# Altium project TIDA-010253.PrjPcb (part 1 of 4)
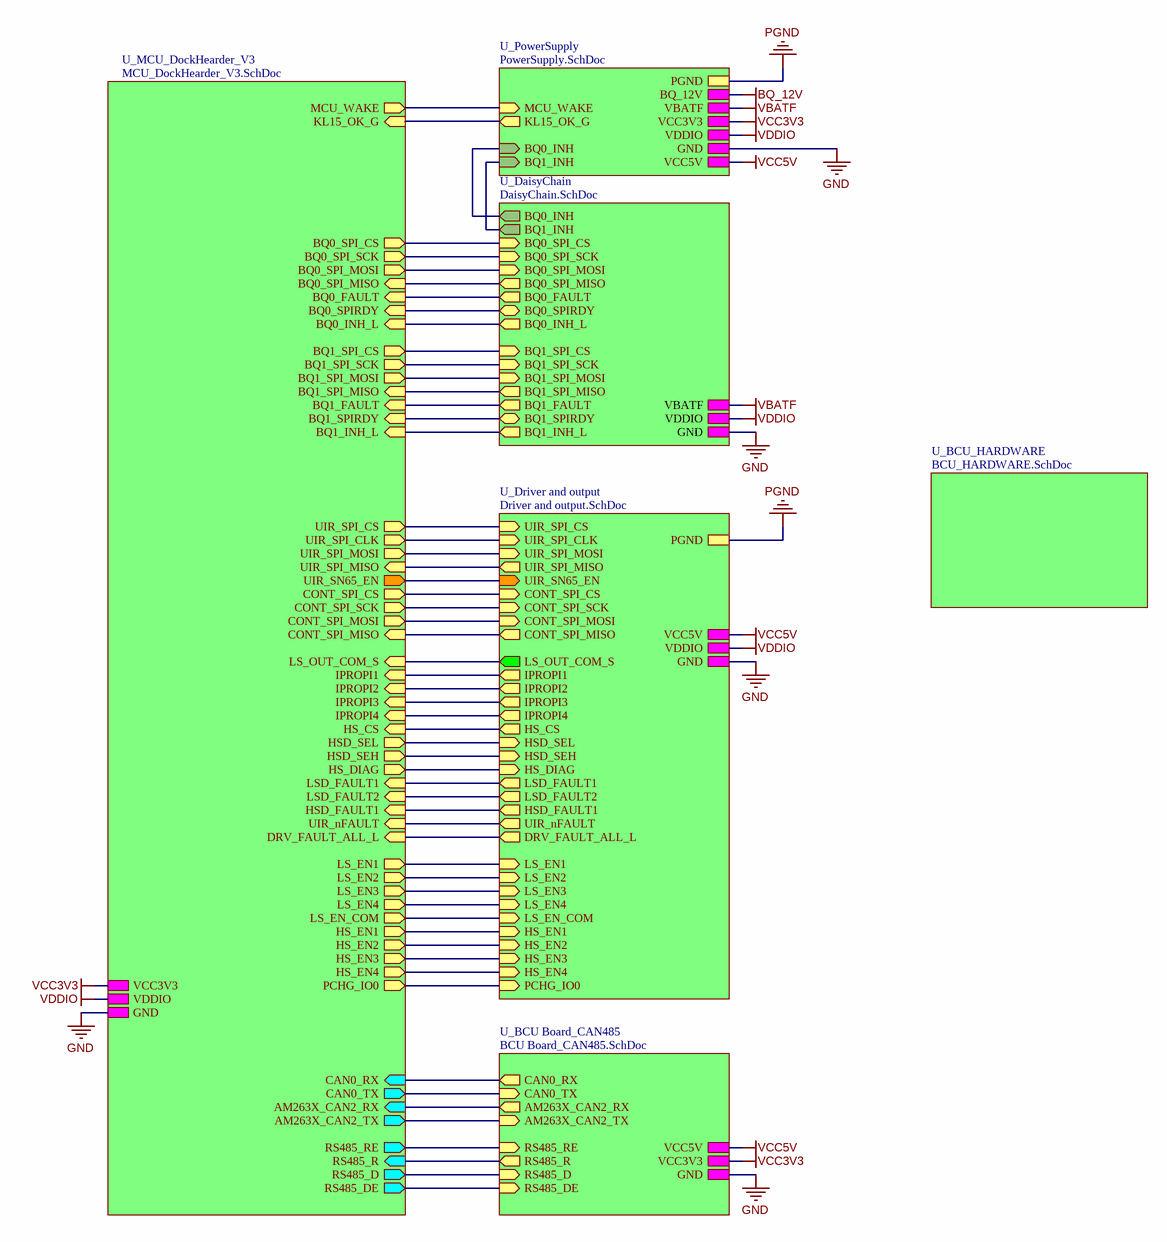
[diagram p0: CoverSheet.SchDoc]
TID: TIDA-010253; TechSupport: http://www.ti.com/support; SCH_Rev: E1; PRJ_Title: Battery Control Unit Reference Design for Energy Storage Systems; PRJ_Number: TIDA-010253; PRJ_Engineer: Enter name of project lead; PRJ_Customer: Public Release; PCB_Rev: E1; PCB_Layout: Junhua Yan; CopyrightYear: 2018
7 sheets, 527 parts. Net scope: hierarchical (ports join the sheet entries above them; power ports are global).
Board file: TIDA-010253.PcbDoc
Sheets:
  CoverSheet.SchDoc
    U_DaisyChain = DaisyChain.SchDoc
    U_PowerSupply = PowerSupply.SchDoc
    U_MCU_DockHearder_V3 = MCU_DockHearder_V3.SchDoc
    U_Driver and output = Driver and output.SchDoc
    U_BCU Board_CAN485 = BCU Board_CAN485.SchDoc
    U_BCU_HARDWARE = BCU_HARDWARE.SchDoc

## Sheet CoverSheet.SchDoc
size A3; Date: Not shown in title block; ApprovedBy: Not shown in title block; CheckedBy: Not shown in title block; Author: Not shown in title block; CompanyName: Not shown in title block; Engineer: Not shown in title block; Organization: Not shown in title block; Address1: Not shown in title block; Address2: Not shown in title block; Address3: Not shown in title block; Address4: Not shown in title block; DocumentNumber: 1; Revision: Use project parameter SCH_Rev; SheetNumber: 1; SheetTotal: 7; PageSetup: Record=PageOptions¦CenterHorizontal=True¦CenterVertical=True¦PrintScale=0.69¦XCorrection=1.00¦YCorrection=1.00¦PrintKind=0¦BorderSize=5000000¦LeftOffset=0¦BottomOffset=0¦Orientation=2¦PaperLength=1000¦PaperWidth=1000¦Scale=100¦PaperSource=15¦PrintQuality=600¦MediaType=1¦DitherType=10¦PaperKind=Letter¦PrintScaleMode=1

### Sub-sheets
U_BCU Board_CAN485 = BCU Board_CAN485.SchDoc: CAN0_TX (in), CAN0_RX (out), AM263X_CAN2_TX (in), AM263X_CAN2_RX (out), RS485_R (out), RS485_RE (in), RS485_DE (in), RS485_D (in), VCC5V, GND, VCC3V3
U_BCU_HARDWARE = BCU_HARDWARE.SchDoc: no entries
U_DaisyChain = DaisyChain.SchDoc: BQ0_SPI_CS (in), BQ0_SPI_SCK (in), BQ0_SPI_MOSI (in), BQ0_SPI_MISO (out), BQ0_SPIRDY (bidir), BQ0_FAULT (out), BQ0_INH_L (out), BQ1_SPI_CS (in), BQ1_SPI_SCK (in), BQ1_SPI_MOSI (in), BQ1_SPI_MISO (out), BQ1_SPIRDY (bidir), BQ1_FAULT (out), BQ1_INH_L (out), VBATF, VDDIO, GND, BQ0_INH (out), BQ1_INH (out)
U_Driver and output = Driver and output.SchDoc: IPROPI1 (out), IPROPI2 (out), IPROPI3 (out), IPROPI4 (out), HS_CS (out), UIR_nFAULT (out), UIR_SN65_EN (in), DRV_FAULT_ALL_L (out), HS_DIAG (in), HSD_SEH (in), HSD_SEL (in), LSD_FAULT1 (out), LSD_FAULT2 (out), HSD_FAULT1 (out), HS_EN4 (in), LS_EN4 (in), LS_EN1 (in), LS_EN_COM (in), HS_EN1 (in), HS_EN3 (in), LS_EN2 (in), HS_EN2 (in), LS_EN3 (in), LS_OUT_COM_S (out), UIR_SPI_MOSI (in), UIR_SPI_MISO (out), UIR_SPI_CS (in), UIR_SPI_CLK (in), CONT_SPI_MOSI (in), CONT_SPI_MISO (out), CONT_SPI_SCK (in), CONT_SPI_CS (in), VCC5V, VDDIO, GND, PCHG_IO0 (in), PGND
U_MCU_DockHearder_V3 = MCU_DockHearder_V3.SchDoc: PCHG_IO0 (out), CAN0_RX (in), CAN0_TX (out), AM263X_CAN2_RX (in), AM263X_CAN2_TX (out), RS485_R (in), RS485_RE (out), RS485_DE (out), RS485_D (out), HSD_SEL (out), HSD_SEH (out), HS_DIAG (out), DRV_FAULT_ALL_L (in), LSD_FAULT1 (in), LSD_FAULT2 (in), HSD_FAULT1 (in), LS_EN4 (out), LS_EN3 (out), LS_EN2 (out), LS_EN1 (out), HS_EN1 (out), HS_EN2 (out), HS_EN3 (out), HS_EN4 (out), UIR_SPI_MOSI (out), UIR_SPI_MISO (in), UIR_SPI_CS (out), UIR_SPI_CLK (out), CONT_SPI_CS (out), CONT_SPI_MOSI (out), CONT_SPI_SCK (out), CONT_SPI_MISO (in), VCC3V3, GND, VDDIO, LS_EN_COM (out), UIR_nFAULT (in), UIR_SN65_EN (out), BQ0_SPI_CS (out), BQ0_SPI_SCK (out), BQ0_SPI_MOSI (out), BQ0_SPI_MISO (in), BQ1_SPI_CS (out), BQ1_SPI_SCK (out), BQ1_SPI_MOSI (out), BQ1_SPI_MISO (in), BQ0_SPIRDY (in), BQ0_FAULT (in), BQ0_INH_L (in), BQ1_SPIRDY (in), BQ1_FAULT (in), BQ1_INH_L (in), KL15_OK_G (in), MCU_WAKE (out), IPROPI1 (in), IPROPI4 (in), IPROPI2 (in), HS_CS (in), IPROPI3 (in), LS_OUT_COM_S (in)
U_PowerSupply = PowerSupply.SchDoc: KL15_OK_G (out), MCU_WAKE (in), BQ0_INH (in), BQ1_INH (in), BQ_12V, VBATF, VCC3V3, VDDIO, GND, VCC5V, PGND

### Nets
GND: sheet U_DaisyChain/GND, sheet U_PowerSupply/GND, sheet U_MCU_DockHearder_V3/GND, sheet U_Driver and output/GND, sheet U_BCU Board_CAN485/GND
PGND: sheet U_PowerSupply/PGND, sheet U_Driver and output/PGND
VBATF: sheet U_DaisyChain/VBATF, sheet U_PowerSupply/VBATF
VCC3V3: sheet U_PowerSupply/VCC3V3, sheet U_MCU_DockHearder_V3/VCC3V3, sheet U_BCU Board_CAN485/VCC3V3
VCC5V: sheet U_PowerSupply/VCC5V, sheet U_Driver and output/VCC5V, sheet U_BCU Board_CAN485/VCC5V
VDDIO: sheet U_DaisyChain/VDDIO, sheet U_PowerSupply/VDDIO, sheet U_MCU_DockHearder_V3/VDDIO, sheet U_Driver and output/VDDIO
AM263X_CAN2_RX: sheet U_MCU_DockHearder_V3/AM263X_CAN2_RX, sheet U_BCU Board_CAN485/AM263X_CAN2_RX
AM263X_CAN2_TX: sheet U_MCU_DockHearder_V3/AM263X_CAN2_TX, sheet U_BCU Board_CAN485/AM263X_CAN2_TX
BQ0_FAULT: sheet U_DaisyChain/BQ0_FAULT, sheet U_MCU_DockHearder_V3/BQ0_FAULT
BQ0_INH: sheet U_DaisyChain/BQ0_INH, sheet U_PowerSupply/BQ0_INH
BQ0_INH_L: sheet U_DaisyChain/BQ0_INH_L, sheet U_MCU_DockHearder_V3/BQ0_INH_L
BQ0_SPI_CS: sheet U_DaisyChain/BQ0_SPI_CS, sheet U_MCU_DockHearder_V3/BQ0_SPI_CS
BQ0_SPI_MISO: sheet U_DaisyChain/BQ0_SPI_MISO, sheet U_MCU_DockHearder_V3/BQ0_SPI_MISO
BQ0_SPI_MOSI: sheet U_DaisyChain/BQ0_SPI_MOSI, sheet U_MCU_DockHearder_V3/BQ0_SPI_MOSI
BQ0_SPI_SCK: sheet U_DaisyChain/BQ0_SPI_SCK, sheet U_MCU_DockHearder_V3/BQ0_SPI_SCK
BQ0_SPIRDY: sheet U_DaisyChain/BQ0_SPIRDY, sheet U_MCU_DockHearder_V3/BQ0_SPIRDY
BQ1_FAULT: sheet U_DaisyChain/BQ1_FAULT, sheet U_MCU_DockHearder_V3/BQ1_FAULT
BQ1_INH: sheet U_DaisyChain/BQ1_INH, sheet U_PowerSupply/BQ1_INH
BQ1_INH_L: sheet U_DaisyChain/BQ1_INH_L, sheet U_MCU_DockHearder_V3/BQ1_INH_L
BQ1_SPI_CS: sheet U_DaisyChain/BQ1_SPI_CS, sheet U_MCU_DockHearder_V3/BQ1_SPI_CS
BQ1_SPI_MISO: sheet U_DaisyChain/BQ1_SPI_MISO, sheet U_MCU_DockHearder_V3/BQ1_SPI_MISO
BQ1_SPI_MOSI: sheet U_DaisyChain/BQ1_SPI_MOSI, sheet U_MCU_DockHearder_V3/BQ1_SPI_MOSI
BQ1_SPI_SCK: sheet U_DaisyChain/BQ1_SPI_SCK, sheet U_MCU_DockHearder_V3/BQ1_SPI_SCK
BQ1_SPIRDY: sheet U_DaisyChain/BQ1_SPIRDY, sheet U_MCU_DockHearder_V3/BQ1_SPIRDY
CAN0_RX: sheet U_MCU_DockHearder_V3/CAN0_RX, sheet U_BCU Board_CAN485/CAN0_RX
CAN0_TX: sheet U_MCU_DockHearder_V3/CAN0_TX, sheet U_BCU Board_CAN485/CAN0_TX
CONT_SPI_CS: sheet U_MCU_DockHearder_V3/CONT_SPI_CS, sheet U_Driver and output/CONT_SPI_CS
CONT_SPI_MISO: sheet U_MCU_DockHearder_V3/CONT_SPI_MISO, sheet U_Driver and output/CONT_SPI_MISO
CONT_SPI_MOSI: sheet U_MCU_DockHearder_V3/CONT_SPI_MOSI, sheet U_Driver and output/CONT_SPI_MOSI
CONT_SPI_SCK: sheet U_MCU_DockHearder_V3/CONT_SPI_SCK, sheet U_Driver and output/CONT_SPI_SCK
DRV_FAULT_ALL_L: sheet U_MCU_DockHearder_V3/DRV_FAULT_ALL_L, sheet U_Driver and output/DRV_FAULT_ALL_L
HS_CS: sheet U_MCU_DockHearder_V3/HS_CS, sheet U_Driver and output/HS_CS
HS_DIAG: sheet U_MCU_DockHearder_V3/HS_DIAG, sheet U_Driver and output/HS_DIAG
HS_EN1: sheet U_MCU_DockHearder_V3/HS_EN1, sheet U_Driver and output/HS_EN1
HS_EN2: sheet U_MCU_DockHearder_V3/HS_EN2, sheet U_Driver and output/HS_EN2
HS_EN3: sheet U_MCU_DockHearder_V3/HS_EN3, sheet U_Driver and output/HS_EN3
HS_EN4: sheet U_MCU_DockHearder_V3/HS_EN4, sheet U_Driver and output/HS_EN4
HSD_FAULT1: sheet U_MCU_DockHearder_V3/HSD_FAULT1, sheet U_Driver and output/HSD_FAULT1
HSD_SEH: sheet U_MCU_DockHearder_V3/HSD_SEH, sheet U_Driver and output/HSD_SEH
HSD_SEL: sheet U_MCU_DockHearder_V3/HSD_SEL, sheet U_Driver and output/HSD_SEL
IPROPI1: sheet U_MCU_DockHearder_V3/IPROPI1, sheet U_Driver and output/IPROPI1
IPROPI2: sheet U_MCU_DockHearder_V3/IPROPI2, sheet U_Driver and output/IPROPI2
IPROPI3: sheet U_MCU_DockHearder_V3/IPROPI3, sheet U_Driver and output/IPROPI3
IPROPI4: sheet U_MCU_DockHearder_V3/IPROPI4, sheet U_Driver and output/IPROPI4
KL15_OK_G: sheet U_PowerSupply/KL15_OK_G, sheet U_MCU_DockHearder_V3/KL15_OK_G
LS_EN1: sheet U_MCU_DockHearder_V3/LS_EN1, sheet U_Driver and output/LS_EN1
LS_EN2: sheet U_MCU_DockHearder_V3/LS_EN2, sheet U_Driver and output/LS_EN2
LS_EN3: sheet U_MCU_DockHearder_V3/LS_EN3, sheet U_Driver and output/LS_EN3
LS_EN4: sheet U_MCU_DockHearder_V3/LS_EN4, sheet U_Driver and output/LS_EN4
LS_EN_COM: sheet U_MCU_DockHearder_V3/LS_EN_COM, sheet U_Driver and output/LS_EN_COM
LS_OUT_COM_S: sheet U_MCU_DockHearder_V3/LS_OUT_COM_S, sheet U_Driver and output/LS_OUT_COM_S
LSD_FAULT1: sheet U_MCU_DockHearder_V3/LSD_FAULT1, sheet U_Driver and output/LSD_FAULT1
LSD_FAULT2: sheet U_MCU_DockHearder_V3/LSD_FAULT2, sheet U_Driver and output/LSD_FAULT2
MCU_WAKE: sheet U_PowerSupply/MCU_WAKE, sheet U_MCU_DockHearder_V3/MCU_WAKE
PCHG_IO0: sheet U_MCU_DockHearder_V3/PCHG_IO0, sheet U_Driver and output/PCHG_IO0
RS485_D: sheet U_MCU_DockHearder_V3/RS485_D, sheet U_BCU Board_CAN485/RS485_D
RS485_DE: sheet U_MCU_DockHearder_V3/RS485_DE, sheet U_BCU Board_CAN485/RS485_DE
RS485_R: sheet U_MCU_DockHearder_V3/RS485_R, sheet U_BCU Board_CAN485/RS485_R
RS485_RE: sheet U_MCU_DockHearder_V3/RS485_RE, sheet U_BCU Board_CAN485/RS485_RE
UIR_nFAULT: sheet U_MCU_DockHearder_V3/UIR_nFAULT, sheet U_Driver and output/UIR_nFAULT
UIR_SN65_EN: sheet U_MCU_DockHearder_V3/UIR_SN65_EN, sheet U_Driver and output/UIR_SN65_EN
UIR_SPI_CLK: sheet U_MCU_DockHearder_V3/UIR_SPI_CLK, sheet U_Driver and output/UIR_SPI_CLK
UIR_SPI_CS: sheet U_MCU_DockHearder_V3/UIR_SPI_CS, sheet U_Driver and output/UIR_SPI_CS
UIR_SPI_MISO: sheet U_MCU_DockHearder_V3/UIR_SPI_MISO, sheet U_Driver and output/UIR_SPI_MISO
UIR_SPI_MOSI: sheet U_MCU_DockHearder_V3/UIR_SPI_MOSI, sheet U_Driver and output/UIR_SPI_MOSI

## Sheet DaisyChain.SchDoc
size A3; Date: Not shown in title block; ApprovedBy: Not shown in title block; CheckedBy: Not shown in title block; Author: Not shown in title block; CompanyName: Not shown in title block; Engineer: Not shown in title block; Organization: Not shown in title block; Address1: Not shown in title block; Address2: Not shown in title block; Address3: Not shown in title block; Address4: Not shown in title block; DocumentNumber: 1; Revision: Use project parameter SCH_Rev; SheetNumber: 3; SheetTotal: 7; PageSetup: Record=PageOptions¦CenterHorizontal=True¦CenterVertical=True¦PrintScale=0.69¦XCorrection=1.00¦YCorrection=1.00¦PrintKind=0¦BorderSize=5000000¦LeftOffset=0¦BottomOffset=0¦Orientation=2¦PaperLength=1000¦PaperWidth=1000¦Scale=100¦PaperSource=15¦PrintQuality=600¦MediaType=1¦DitherType=10¦PaperKind=Letter¦PrintScaleMode=1
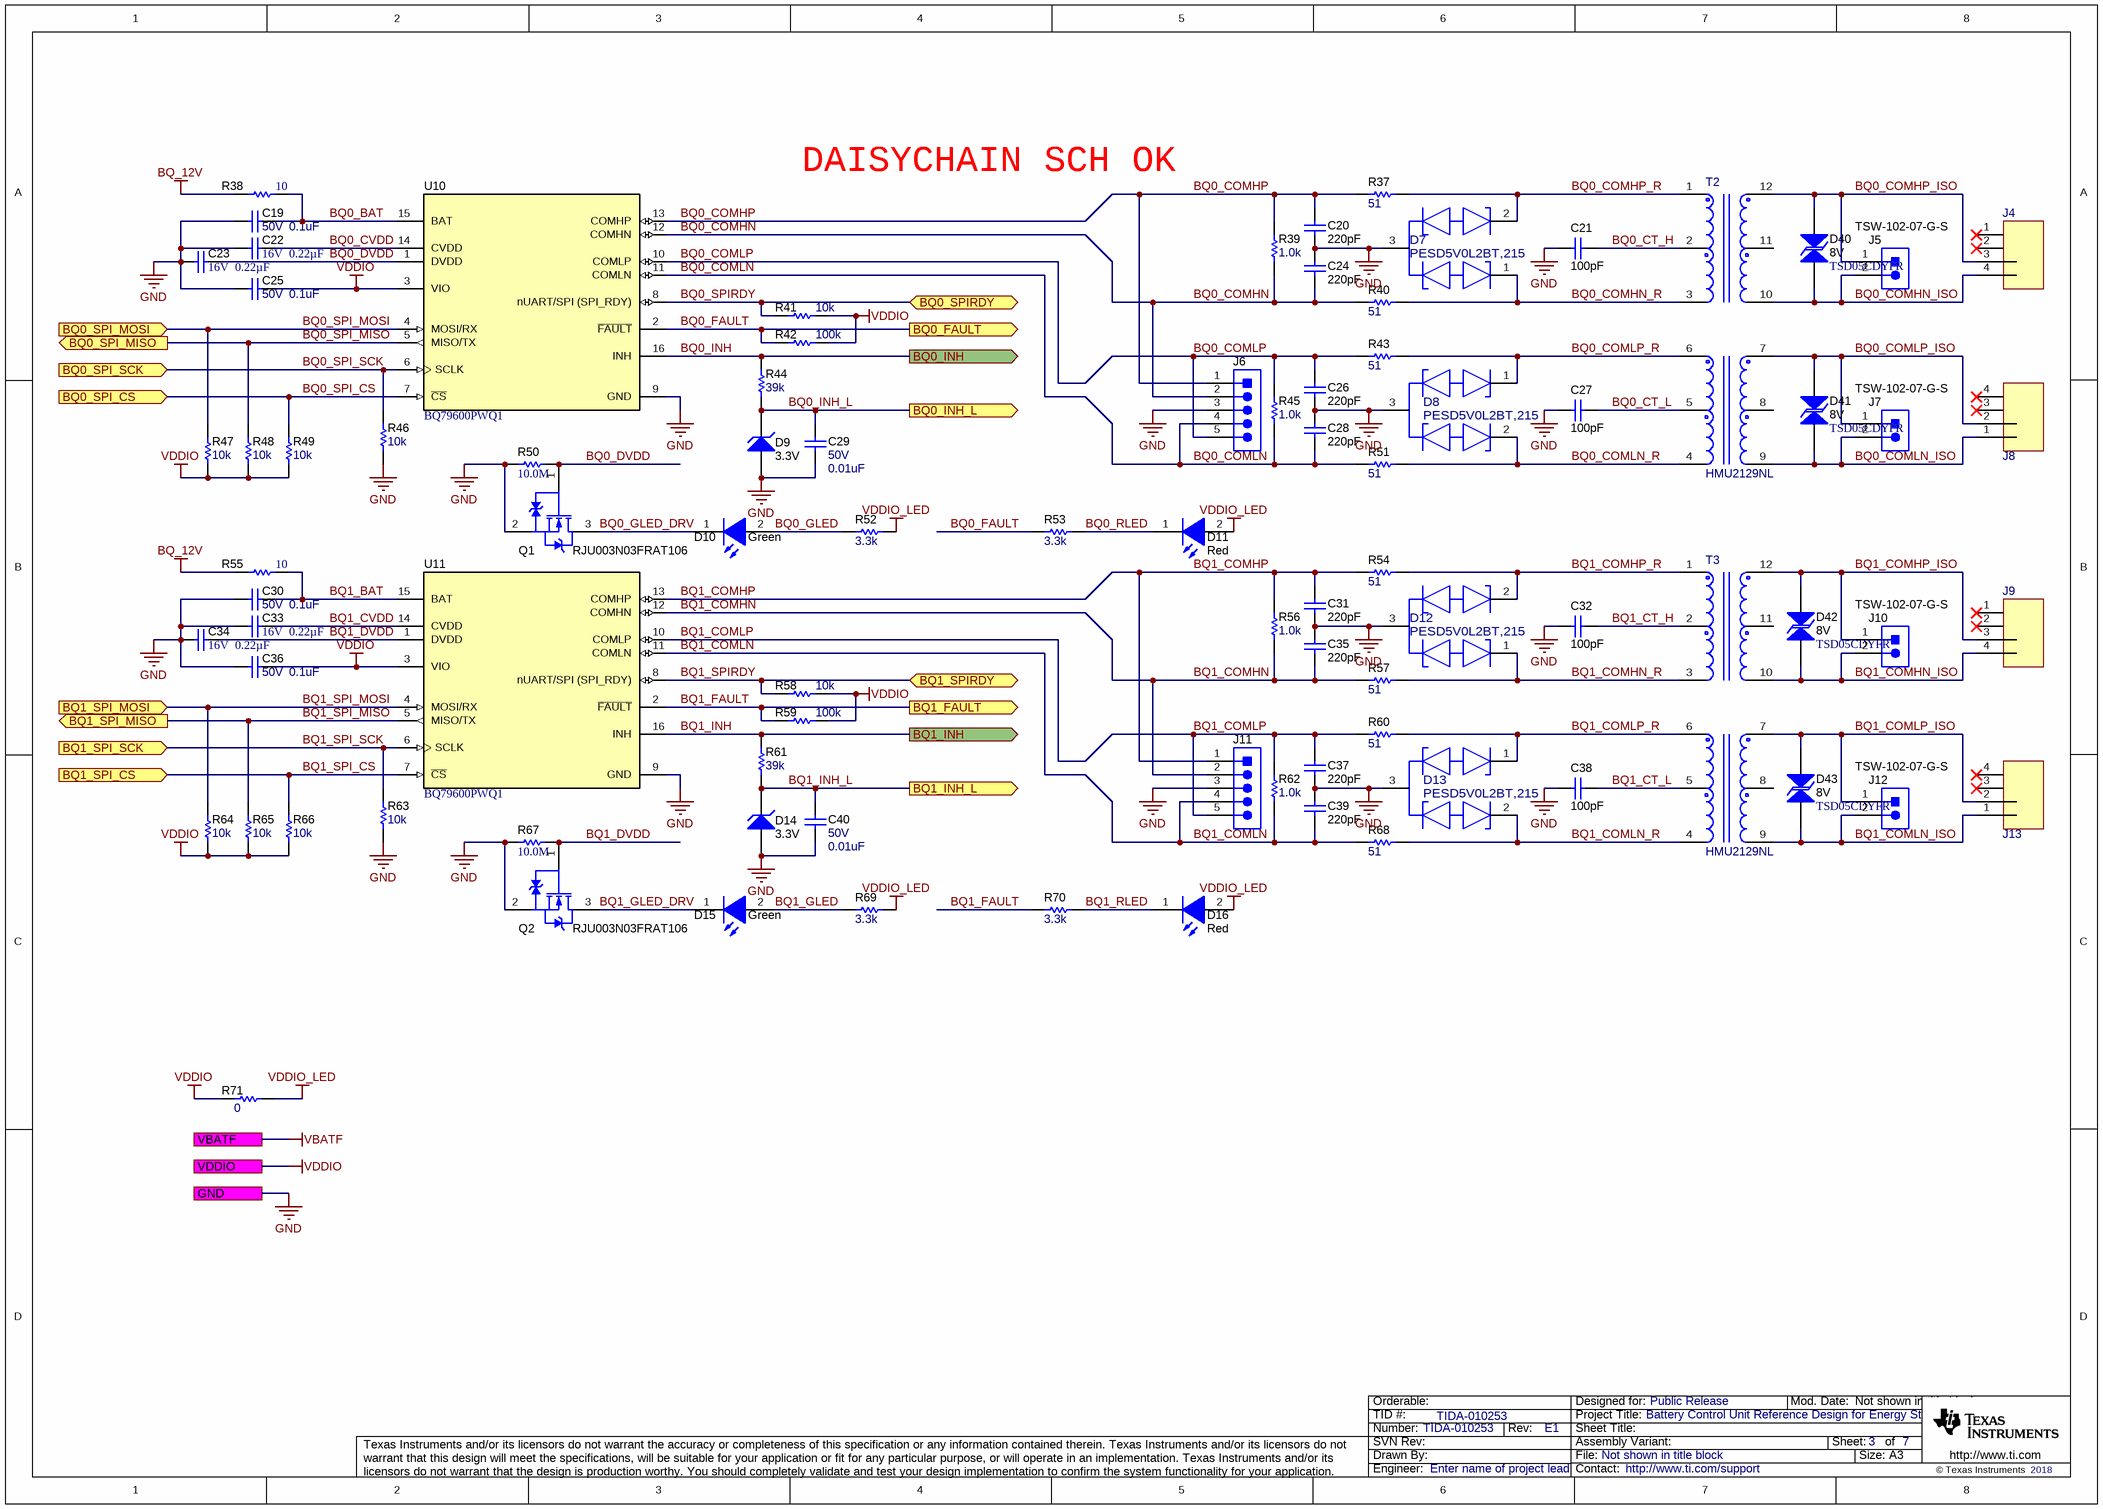
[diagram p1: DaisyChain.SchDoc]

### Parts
C19  VDC_V: 50V  ValueDisplayed: 0.1uF  [0402]  (hidden comment: GCM155R71H104KE02D)
C20  Cap_F: 220pF  [0603]  (hidden comment: CL10B221JB8NNNC)
C21  ValueDisplayed: 100pF  [0603]  (hidden comment: GCM1885C1H101JA16J)
C22  VDC_V: 16V  ValueDisplayed: 0.22µF  [0402]  (hidden comment: GCM155R71C224KE02D)
C23  VDC_V: 16V  ValueDisplayed: 0.22µF  [0402]  (hidden comment: GCM155R71C224KE02D)
C24  Cap_F: 220pF  [0603]  (hidden comment: CL10B221JB8NNNC)
C25  VDC_V: 50V  ValueDisplayed: 0.1uF  [0402]  (hidden comment: GCM155R71H104KE02D)
C26  Cap_F: 220pF  [0603]  (hidden comment: CL10B221JB8NNNC)
C27  ValueDisplayed: 100pF  [0603]  (hidden comment: GCM1885C1H101JA16J)
C28  Cap_F: 220pF  [0603]  (hidden comment: CL10B221JB8NNNC)
C29  VDC_V: 50V  ValueDisplayed: 0.01uF  [0402]  (hidden comment: CGA2B3X7R1H103K050BB)
C30  VDC_V: 50V  ValueDisplayed: 0.1uF  [0402]  (hidden comment: GCM155R71H104KE02D)
C31  Cap_F: 220pF  [0603]  (hidden comment: CL10B221JB8NNNC)
C32  ValueDisplayed: 100pF  [0603]  (hidden comment: GCM1885C1H101JA16J)
C33  VDC_V: 16V  ValueDisplayed: 0.22µF  [0402]  (hidden comment: GCM155R71C224KE02D)
C34  VDC_V: 16V  ValueDisplayed: 0.22µF  [0402]  (hidden comment: GCM155R71C224KE02D)
C35  Cap_F: 220pF  [0603]  (hidden comment: CL10B221JB8NNNC)
C36  VDC_V: 50V  ValueDisplayed: 0.1uF  [0402]  (hidden comment: GCM155R71H104KE02D)
C37  Cap_F: 220pF  [0603]  (hidden comment: CL10B221JB8NNNC)
C38  ValueDisplayed: 100pF  [0603]  (hidden comment: GCM1885C1H101JA16J)
C39  Cap_F: 220pF  [0603]  (hidden comment: CL10B221JB8NNNC)
C40  VDC_V: 50V  ValueDisplayed: 0.01uF  [0402]  (hidden comment: CGA2B3X7R1H103K050BB)
D7  PESD5V0L2BT,215  [FP-PESD5V0L2BT,215_SOT23-3-MFG]
D8  PESD5V0L2BT,215  [FP-PESD5V0L2BT,215_SOT23-3-MFG]
D9  value 3.3V  [SOD-323]  (hidden comment: SZMM3Z3V3ST1G)
D10  value Green  [WL-SMCW_GREEN]  (hidden comment: 150060VS75000)
D11  value Red  [WL-SMCW_RED]  (hidden comment: 150060RS75000)
D12  PESD5V0L2BT,215  [FP-PESD5V0L2BT,215_SOT23-3-MFG]
D13  PESD5V0L2BT,215  [FP-PESD5V0L2BT,215_SOT23-3-MFG]
D14  value 3.3V  [SOD-323]  (hidden comment: SZMM3Z3V3ST1G)
D15  value Green  [WL-SMCW_GREEN]  (hidden comment: 150060VS75000)
D16  value Red  [WL-SMCW_RED]  (hidden comment: 150060RS75000)
D40  value 8V  PartNumber: TSD05CDYFR  [SOD-323-Bi]  (hidden comment: CDSOD323-T08SC)
D41  value 8V  PartNumber: TSD05CDYFR  [SOD-323-Bi]  (hidden comment: CDSOD323-T08SC)
D42  value 8V  PartNumber: TSD05CDYFR  [SOD-323-Bi]  (hidden comment: CDSOD323-T08SC)
D43  value 8V  PartNumber: TSD05CDYFR  [SOD-323-Bi]  (hidden comment: CDSOD323-T08SC)
J4  DaisyChainConn_CoLay_34  [DaisyChainConn_CoLay_34]  (value not drawn)
J5  TSW-102-07-G-S  [TSW-102-07-G-S]
J6  TSW-105-07-G-S  [TSW-105-07-X-S]  (value not drawn)
J7  TSW-102-07-G-S  [TSW-102-07-G-S]
J8  DaisyChainConn_CoLay_12  [DaisyChainConn_CoLay_12]  (value not drawn)
J9  DaisyChainConn_CoLay_34  [DaisyChainConn_CoLay_34]  (value not drawn)
J10  TSW-102-07-G-S  [TSW-102-07-G-S]
J11  TSW-105-07-G-S  [TSW-105-07-X-S]  (value not drawn)
J12  TSW-102-07-G-S  [TSW-102-07-G-S]
J13  DaisyChainConn_CoLay_12  [DaisyChainConn_CoLay_12]  (value not drawn)
Q1  RJU003N03FRAT106  [SOT-323]
Q2  RJU003N03FRAT106  [SOT-323]
R37  ValueDisplayed: 51  [0603]  (hidden comment: CRCW060351R0JNEA)
R38  ValueDisplayed: 10  [0603]  (hidden comment: CRCW060310R0JNEA)
R39  ValueDisplayed: 1.0k  [0603]  (hidden comment: CRCW06031K00JNEA)
R40  ValueDisplayed: 51  [0603]  (hidden comment: CRCW060351R0JNEA)
R41  ValueDisplayed: 10k  [0402]  (hidden comment: CRCW040210K0JNED)
R42  ValueDisplayed: 100k  [0402]  (hidden comment: CRCW0402100KJNED)
R43  ValueDisplayed: 51  [0603]  (hidden comment: CRCW060351R0JNEA)
R44  ValueDisplayed: 39k  [0402]  (hidden comment: CRCW040239K0JNED)
R45  ValueDisplayed: 1.0k  [0603]  (hidden comment: CRCW06031K00JNEA)
R46  ValueDisplayed: 10k  [0402]  (hidden comment: CRCW040210K0JNED)
R47  ValueDisplayed: 10k  [0402]  (hidden comment: CRCW040210K0JNED)
R48  ValueDisplayed: 10k  [0402]  (hidden comment: CRCW040210K0JNED)
R49  ValueDisplayed: 10k  [0402]  (hidden comment: CRCW040210K0JNED)
R50  ValueDisplayed: 10.0M  [0402]  (hidden comment: CRCW040210M0FKED)
R51  ValueDisplayed: 51  [0603]  (hidden comment: CRCW060351R0JNEA)
R52  ValueDisplayed: 3.3k  [0402]  (hidden comment: CRCW04023K30JNED)
R53  ValueDisplayed: 3.3k  [0402]  (hidden comment: CRCW04023K30JNED)
R54  ValueDisplayed: 51  [0603]  (hidden comment: CRCW060351R0JNEA)
R55  ValueDisplayed: 10  [0603]  (hidden comment: CRCW060310R0JNEA)
R56  ValueDisplayed: 1.0k  [0603]  (hidden comment: CRCW06031K00JNEA)
R57  ValueDisplayed: 51  [0603]  (hidden comment: CRCW060351R0JNEA)
R58  ValueDisplayed: 10k  [0402]  (hidden comment: CRCW040210K0JNED)
R59  ValueDisplayed: 100k  [0402]  (hidden comment: CRCW0402100KJNED)
R60  ValueDisplayed: 51  [0603]  (hidden comment: CRCW060351R0JNEA)
R61  ValueDisplayed: 39k  [0402]  (hidden comment: CRCW040239K0JNED)
R62  ValueDisplayed: 1.0k  [0603]  (hidden comment: CRCW06031K00JNEA)
R63  ValueDisplayed: 10k  [0402]  (hidden comment: CRCW040210K0JNED)
R64  ValueDisplayed: 10k  [0402]  (hidden comment: CRCW040210K0JNED)
R65  ValueDisplayed: 10k  [0402]  (hidden comment: CRCW040210K0JNED)
R66  ValueDisplayed: 10k  [0402]  (hidden comment: CRCW040210K0JNED)
R67  ValueDisplayed: 10.0M  [0402]  (hidden comment: CRCW040210M0FKED)
R68  ValueDisplayed: 51  [0603]  (hidden comment: CRCW060351R0JNEA)
R69  ValueDisplayed: 3.3k  [0402]  (hidden comment: CRCW04023K30JNED)
R70  ValueDisplayed: 3.3k  [0402]  (hidden comment: CRCW04023K30JNED)
R71  ValueDisplayed: 0  [0603]  (hidden comment: CRCW06030000Z0EA)
T2  HMU2129NL  [HMU2129NL]
T3  HMU2129NL  [HMU2129NL]
U10  BQ79600PWQ1  [PW0016A_N]
U11  BQ79600PWQ1  [PW0016A_N]

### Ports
BQ0_FAULT (out), BQ0_INH (out), BQ0_INH_L (out), BQ0_SPI_CS (in), BQ0_SPI_MISO (out), BQ0_SPI_MOSI (in), BQ0_SPI_SCK (in), BQ0_SPIRDY (bidir), BQ1_FAULT (out), BQ1_INH (out), BQ1_INH_L (out), BQ1_SPI_CS (in), BQ1_SPI_MISO (out), BQ1_SPI_MOSI (in), BQ1_SPI_SCK (in), BQ1_SPIRDY (bidir), GND, VBATF, VDDIO

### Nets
BQ_12V: R38.2 R55.2
GND: C19.2 C20.2 C21.1 C22.2 C23.2 C24.1 C25.2 C26.2 C27.1 C28.1 C29.2 C30.2 C31.2 C32.1 C33.2 C34.2 C35.1 C36.2 C37.2 C38.1 C39.1 C40.2 D7.3(double_cathode) D8.3(double_cathode) D9.2(A) D12.3(double_cathode) D13.3(double_cathode) D14.2(A) J6.3 J11.3 Q1.2(S) Q2.2(S) R46.1 R50.2 R63.1 R67.2 U10.9(GND) U11.9(GND) ; port GND
VDDIO: C25.1 C36.1 R41.2 R42.2 R47.1 R48.1 R49.1 R58.2 R59.2 R64.1 R65.1 R66.1 R71.1 U10.3(VIO) U11.3(VIO) ; port VDDIO
VDDIO_LED: D11.2(A) D16.2(A) R52.2 R69.2 R71.2
BQ0_BAT: C19.1 R38.1 U10.15(BAT)
BQ0_COMHN: C24.2 J6.2 R39.1 R40.1 U10.12(COMHN)
BQ0_COMHN_ISO: D40.1 J4.4 J5.2 T2.10(TX-)
BQ0_COMHN_R: D7.1(cathode_1) R40.2 T2.3(TD-)
BQ0_COMHP: C20.1 J6.1 R37.1 R39.2 U10.13(COMHP)
BQ0_COMHP_ISO: D40.2 J4.3 J5.1 T2.12(TX+)
BQ0_COMHP_R: D7.2(cathode_2) R37.2 T2.1(TD+)
BQ0_COMLN: C28.2 J6.4 R45.1 R51.1 U10.11(COMLN)
BQ0_COMLN_ISO: D41.1 J7.2 J8.1 T2.9(TX+)
BQ0_COMLN_R: D8.2(cathode_2) R51.2 T2.4(TD+)
BQ0_COMLP: C26.1 J6.5 R43.1 R45.2 U10.10(COMLP)
BQ0_COMLP_ISO: D41.2 J7.1 J8.2 T2.7(TX-)
BQ0_COMLP_R: D8.1(cathode_1) R43.2 T2.6(TD-)
BQ0_CT_H: C21.2 T2.2(TCT)
BQ0_CT_L: C27.2 T2.5(TCT)
BQ0_CVDD: C22.1 U10.14(CVDD)
BQ0_DVDD: C23.1 Q1.1(G) R50.1 U10.1(DVDD)
BQ0_FAULT: R42.1 R53.1 U10.2(~{FAULT}) ; port BQ0_FAULT
BQ0_GLED: D10.2(A) R52.1
BQ0_GLED_DRV: D10.1(K) Q1.3(D)
BQ0_INH: R44.2 U10.16(INH) ; port BQ0_INH
BQ0_INH_L: C29.1 D9.1(K) R44.1 ; port BQ0_INH_L
BQ0_RLED: D11.1(K) R53.2
BQ0_SPI_CS: R49.2 U10.7(~{CS}) ; port BQ0_SPI_CS
BQ0_SPI_MISO: R48.2 U10.5(MISO/TX) ; port BQ0_SPI_MISO
BQ0_SPI_MOSI: R47.2 U10.4(MOSI/RX) ; port BQ0_SPI_MOSI
BQ0_SPI_SCK: R46.2 U10.6(SCLK) ; port BQ0_SPI_SCK
BQ0_SPIRDY: R41.1 U10.8(nUART/SPI_(SPI_RDY)) ; port BQ0_SPIRDY
BQ1_BAT: C30.1 R55.1 U11.15(BAT)
BQ1_COMHN: C35.2 J11.2 R56.1 R57.1 U11.12(COMHN)
BQ1_COMHN_ISO: D42.1 J9.4 J10.2 T3.10(TX-)
BQ1_COMHN_R: D12.1(cathode_1) R57.2 T3.3(TD-)
BQ1_COMHP: C31.1 J11.1 R54.1 R56.2 U11.13(COMHP)
BQ1_COMHP_ISO: D42.2 J9.3 J10.1 T3.12(TX+)
BQ1_COMHP_R: D12.2(cathode_2) R54.2 T3.1(TD+)
BQ1_COMLN: C39.2 J11.4 R62.1 R68.1 U11.11(COMLN)
BQ1_COMLN_ISO: D43.1 J12.2 J13.1 T3.9(TX+)
BQ1_COMLN_R: D13.2(cathode_2) R68.2 T3.4(TD+)
BQ1_COMLP: C37.1 J11.5 R60.1 R62.2 U11.10(COMLP)
BQ1_COMLP_ISO: D43.2 J12.1 J13.2 T3.7(TX-)
BQ1_COMLP_R: D13.1(cathode_1) R60.2 T3.6(TD-)
BQ1_CT_H: C32.2 T3.2(TCT)
BQ1_CT_L: C38.2 T3.5(TCT)
BQ1_CVDD: C33.1 U11.14(CVDD)
BQ1_DVDD: C34.1 Q2.1(G) R67.1 U11.1(DVDD)
BQ1_FAULT: R59.1 R70.1 U11.2(~{FAULT}) ; port BQ1_FAULT
BQ1_GLED: D15.2(A) R69.1
BQ1_GLED_DRV: D15.1(K) Q2.3(D)
BQ1_INH: R61.2 U11.16(INH) ; port BQ1_INH
BQ1_INH_L: C40.1 D14.1(K) R61.1 ; port BQ1_INH_L
BQ1_RLED: D16.1(K) R70.2
BQ1_SPI_CS: R66.2 U11.7(~{CS}) ; port BQ1_SPI_CS
BQ1_SPI_MISO: R65.2 U11.5(MISO/TX) ; port BQ1_SPI_MISO
BQ1_SPI_MOSI: R64.2 U11.4(MOSI/RX) ; port BQ1_SPI_MOSI
BQ1_SPI_SCK: R63.2 U11.6(SCLK) ; port BQ1_SPI_SCK
BQ1_SPIRDY: R58.1 U11.8(nUART/SPI_(SPI_RDY)) ; port BQ1_SPIRDY

Not connected (* = marked no-connect by the designer): J4 1* 2*; J8 3* 4*; J9 1* 2*; J13 3* 4*; T2 8(CMT) 11(CMT); T3 8(CMT) 11(CMT)

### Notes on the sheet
- DAISYCHAIN SCH OK

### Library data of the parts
C19 C25 C30 C36 = CMP-0006356-2: CAP, CERM, 0.1 uF, 50 V, +/- 10%, X7R, AEC-Q200 Grade 1, 0402; Manufacturer: MuRata; TaMin_C: -55°C; Polarized: N; SizeAreaWB_mm2: 3; Value1: Unknown; U/M: EA; Value: 0.1uF; TaMax_C: 125°C; SizeZ_mm: 0.6; SizeX_mm: 1; SizeY_mm: 0.5; AEC Qualified: Y; Cap_F: 100nF; AEC Category: Q200
C20 C24 C26 C28 C31 C35 C37 C39 = CMP-0860329-1: CAP, CERM, 220 pF, 50 V,+/- 5%, X7R, 0603; Manufacturer: Samsung Electro-Mechanics; TaMin_C: -55°C; Polarized: N; SizeAreaWB_mm2: 4.68; U/M: EA; Value: 220pF; TaMax_C: 125°C; SizeZ_mm: 1; SizeX_mm: 1.6; SizeY_mm: 0.8; Value2: 50V; SizeArea_mm2: 1.28; CompType: Capacitor; AEC Category: Q200
C21 C27 C32 C38 = CMP-0750041-1: CAP, CERM, 100 pF, 50 V,+/- 5%, C0G/NP0, AEC-Q200 Grade 1, 0603; Manufacturer: MuRata; TaMin_C: -55°C; Polarized: N; SizeAreaWB_mm2: 4.68; U/M: EA; Value: 100pF; TaMax_C: 125°C; SizeZ_mm: 1; SizeX_mm: 1.6; SizeY_mm: 0.8; Value2: 50V; SizeArea_mm2: 1.28; AEC Qualified: Y; AEC Category: Q200
C22 C23 C33 C34 = CMP-0078265-1: CAP, CERM, 0.22 µF, 16 V,+/- 10%, X7R, AEC-Q200 Grade 1, 0402; Manufacturer: MuRata; TaMin_C: -55°C; Polarized: N; SizeAreaWB_mm2: 3; U/M: EA; Value: 0.22uF; TaMax_C: 125°C; SizeZ_mm: 0.6; SizeX_mm: 1; SizeY_mm: 0.5; AEC Qualified: Y; Cap_F: 220nF; AEC Category: Q200
C29 C40 = CMP-0006324-2: CAP, CERM, 0.01 uF, 50 V, +/- 10%, X7R, AEC-Q200 Grade 1, 0402; Manufacturer: TDK; TaMin_C: -55°C; ESR_ohm: 3.33065d; Polarized: N; SizeAreaWB_mm2: 3; Value1: 0.333065 ohm; U/M: EA; Value: 0.01uF; TaMax_C: 125°C; SizeZ_mm: 0.6; SizeX_mm: 1; SizeY_mm: 0.5; AEC Qualified: Y; Cap_F: 10nF; IRMS_A: 3.23373dA; AEC Category: Q200
D7 D8 D12 D13 = CMP-0086523-1: 28V Clamp 13A (8/20µs) Ipp Tvs Diode Surface Mount TO-236AB; Manufacturer: Nexperia; SizeZ_mm: 1.1mm; AEC Qualified: No
D9 D14 = CMP-0085730-1: Diode, Zener, 3.3 V, 300 mW, AEC-Q101, SOD-323; Manufacturer: ON Semiconductor; RJA_CperW: 416; AEC Qualified: Y; SizeArea_mm2: 3.645; SizeX_mm: 2.7; SizeY_mm: 1.35; SizeZ_mm: 1; AEC Category: Q101; SizeAreaWB_mm2: 8.695; Power_W: 300mW; Value1: 0.3W
D10 D15 = CMP-0002894-2: LED, Green, SMD; Manufacturer: Wurth Elektronik; Type: AlInGaP; Value2: 2V; Io_A: 20mA; Value1: W
D11 D16 = CMP-0002947-3: LED, Red, SMD; Manufacturer: Wurth Elektronik; Value1: 0.072W; Vf_V: 2V; Angle: 140; Tjmax_C: 85°C; Type: AlInGaP; Vr_V: 5V; Io_A: 30mA; Power_TotalModule: 72mW
D40-D43 = CMP-0065114-2: Diode, TVS, Bi, 8 V, 18.5 Vc, SOD-323; Manufacturer: Bourns; SizeAreaWB_mm2: 8.695; Ppk: 400W; SizeArea_mm2: 3.645; AEC Qualified: N; SizeY_mm: 1.35; Ipp: 17A; Vbr_Min: 8.5V; Vc: 18.5V; SizeZ_mm: 1.0; SizeX_mm: 2.7; AEC Category: Q101
J5 J7 J10 J12 = CMP-0075405-3: Header, 100mil, 2x1, Gold, TH; Manufacturer: Samtec; Current_A: 6.3A; Green_Lifecycle: Active; Pitch_mm: 2.54; Cert_CSA: Y; Cert_VDE: N; Green_REACh: Passed; Row_Count: 1; Gender: Male; Voltage_V: 550V
J6 J11 = CMP-0075411-1: Header, 100mil, 5x1, Gold, TH; Manufacturer: Samtec; Pitch_mm: 2.54; Cert_VDE: N; Gender: Male; Cert_CSA: Y; Voltage_V: 550V; Green_REACh: Passed; Current_A: 6.3A; CT: False; Green_Lifecycle: Active; Row_Count: 1; CNHeader: True
Q1 Q2 = CMP-0067562-1: MOSFET, N-CH, 30 V, 0.3 A, AEC-Q101, SOT-323; Alternate Manufacturer: None; Manufacturer: Rohm; Rdson45_ohm: 1.1; SizeAreaWB_mm2: 10.24; Vgs_V: 12V; Value1: 1.1 ohm; VdsMax_V: 30V; U/M: EA; Value: 30V; IdsMax_A: 3dA; SizeX_mm: 2.2; Value2: ? nC; SizeArea_mm2: 4.84; ChType: N; AEC Qualified: Y; AEC Category: Q101
R37 R40 R43 R51 R54 R57 R60 R68 = CMP-0025825-4: RES, 51, 5%, 0.1 W, AEC-Q200 Grade 0, 0603; Manufacturer: Vishay-Dale; Power_W: 100mW; TempCo: 200 ppm/C; Value_Code: 51R0; Value: 51; EIA_Code: E24; SizeX_mm: 1.6; SizeY_mm: 0.8; SizeZ_mm: 1; Value2: 0.1W; SizeArea_mm2: 1.28; AEC Qualified: Y; VDC_V: 75V; AEC Category: Q200; AEC Grade: 0
R38 R55 = CMP-0025703-4: RES, 10, 5%, 0.1 W, AEC-Q200 Grade 0, 0603; Manufacturer: Vishay-Dale; Power_W: 100mW; TempCo: 200 ppm/C; Value_Code: 10R0; Value: 10; EIA_Code: E24; SizeX_mm: 1.6; SizeY_mm: 0.8; SizeZ_mm: 1; Value2: 0.1W; SizeArea_mm2: 1.28; AEC Qualified: Y; VDC_V: 75V; AEC Category: Q200; AEC Grade: 0
R39 R45 R56 R62 = CMP-0025729-4: RES, 1.0 k, 5%, 0.1 W, AEC-Q200 Grade 0, 0603; Manufacturer: Vishay-Dale; Power_W: 100mW; TempCo: 200 ppm/C; Value_Code: 1k00; Value: 1.0k; EIA_Code: E24; Res_ohm: 1k; SizeX_mm: 1.6; SizeY_mm: 0.8; SizeZ_mm: 1; Value2: 0.1W; SizeArea_mm2: 1.28; AEC Qualified: Y; VDC_V: 75V; AEC Category: Q200; AEC Grade: 0
R41 R46-R49 R58 R63-R66 = CMP-0026825-5: RES, 10 k, 5%, 0.063 W, AEC-Q200 Grade 0, 0402; Manufacturer: Vishay-Dale; Power_W: 63mW; TempCo: 200 ppm/C; Value_Code: 10k0; Value: 10k; EIA_Code: E24; SizeX_mm: 1; SizeY_mm: 0.5; SizeZ_mm: 0.6; Value2: 0.063W; AEC Qualified: Y; VDC_V: 50V; AEC Category: Q200; AEC Grade: 0
R42 R59 = CMP-0026823-3: RES, 100 k, 5%, 0.063 W, AEC-Q200 Grade 0, 0402; Manufacturer: Vishay-Dale; Power_W: 63mW; TempCo: 200 ppm/C; Value: 100k; EIA_Code: E24; SizeX_mm: 1; SizeY_mm: 0.5; SizeZ_mm: 0.6; Value2: 0.063W; AEC Qualified: Y; VDC_V: 50V; AEC Category: Q200; AEC Grade: 0
R44 R61 = CMP-0026915-3: RES, 39 k, 5%, 0.063 W, AEC-Q200 Grade 0, 0402; Manufacturer: Vishay-Dale; Power_W: 63mW; TempCo: 200 ppm/C; Value_Code: 39k0; Value: 39k; EIA_Code: E24; SizeX_mm: 1; SizeY_mm: 0.5; SizeZ_mm: 0.6; Value2: 0.063W; AEC Qualified: Y; VDC_V: 50V; AEC Category: Q200; AEC Grade: 0
R50 R67 = CMP-0025962-3: RES, 10.0 M, 1%, 0.063 W, AEC-Q200 Grade 0, 0402; Manufacturer: Vishay-Dale; Power_W: 63mW; TempCo: 100 ppm/C; Value_Code: 10M0; Value: 10.0Meg; EIA_Code: E96; Res_ohm: 10M; SizeX_mm: 1; SizeY_mm: 0.5; SizeZ_mm: 0.6; Value2: 0.063W; AEC Qualified: Y; VDC_V: 50V; AEC Category: Q200; AEC Grade: 0
R52 R53 R69 R70 = CMP-0026918-5: RES, 3.3 k, 5%, 0.063 W, AEC-Q200 Grade 0, 0402; Manufacturer: Vishay-Dale; Power_W: 63mW; TempCo: 200 ppm/C; Value_Code: 3k30; Value: 3.3k; EIA_Code: E24; SizeX_mm: 1; SizeY_mm: 0.5; SizeZ_mm: 0.6; Value2: 0.063W; AEC Qualified: Y; VDC_V: 50V; AEC Category: Q200; AEC Grade: 0
R71 = CMP-0025697-4: RES, 0, 5%, 0.1 W, AEC-Q200 Grade 0, 0603; Manufacturer: Vishay-Dale; Power_W: 100mW; TempCo: 200 ppm/C; Value_Code: 0000; Value: 0; EIA_Code: E24; SizeX_mm: 1.6; SizeY_mm: 0.8; SizeZ_mm: 1; Value2: 0.1W; SizeArea_mm2: 1.28; AEC Qualified: Y; VDC_V: 75V; AEC Category: Q200
T2 T3 = HMU2129NL: BMS TRANSFORMER
U10 U11 = CMP-0860051-2: BQ79600PWQ1, PW0016A (TSSOP-16); Manufacturer: Texas Instruments; AEC Qualified: Y; SizeX_mm: 6.4; CompType: IC; AEC Category: Q200; SizeAreaWB_mm2: 58.8; SizeArea_mm2: 32; SizeZ_mm: 1.2; SizeY_mm: 5

## Sheet PowerSupply.SchDoc
size A3; Date: Not shown in title block; ApprovedBy: Not shown in title block; CheckedBy: Not shown in title block; Author: Not shown in title block; CompanyName: Not shown in title block; Engineer: Not shown in title block; Organization: Not shown in title block; Address1: Not shown in title block; Address2: Not shown in title block; Address3: Not shown in title block; Address4: Not shown in title block; DocumentNumber: 1; Revision: Use project parameter SCH_Rev; SheetNumber: 5; SheetTotal: 7; PageSetup: Record=PageOptions¦CenterHorizontal=True¦CenterVertical=True¦PrintScale=0.69¦XCorrection=1.00¦YCorrection=1.00¦PrintKind=0¦BorderSize=5000000¦LeftOffset=0¦BottomOffset=0¦Orientation=2¦PaperLength=1000¦PaperWidth=1000¦Scale=100¦PaperSource=15¦PrintQuality=600¦MediaType=1¦DitherType=10¦PaperKind=Letter¦PrintScaleMode=1
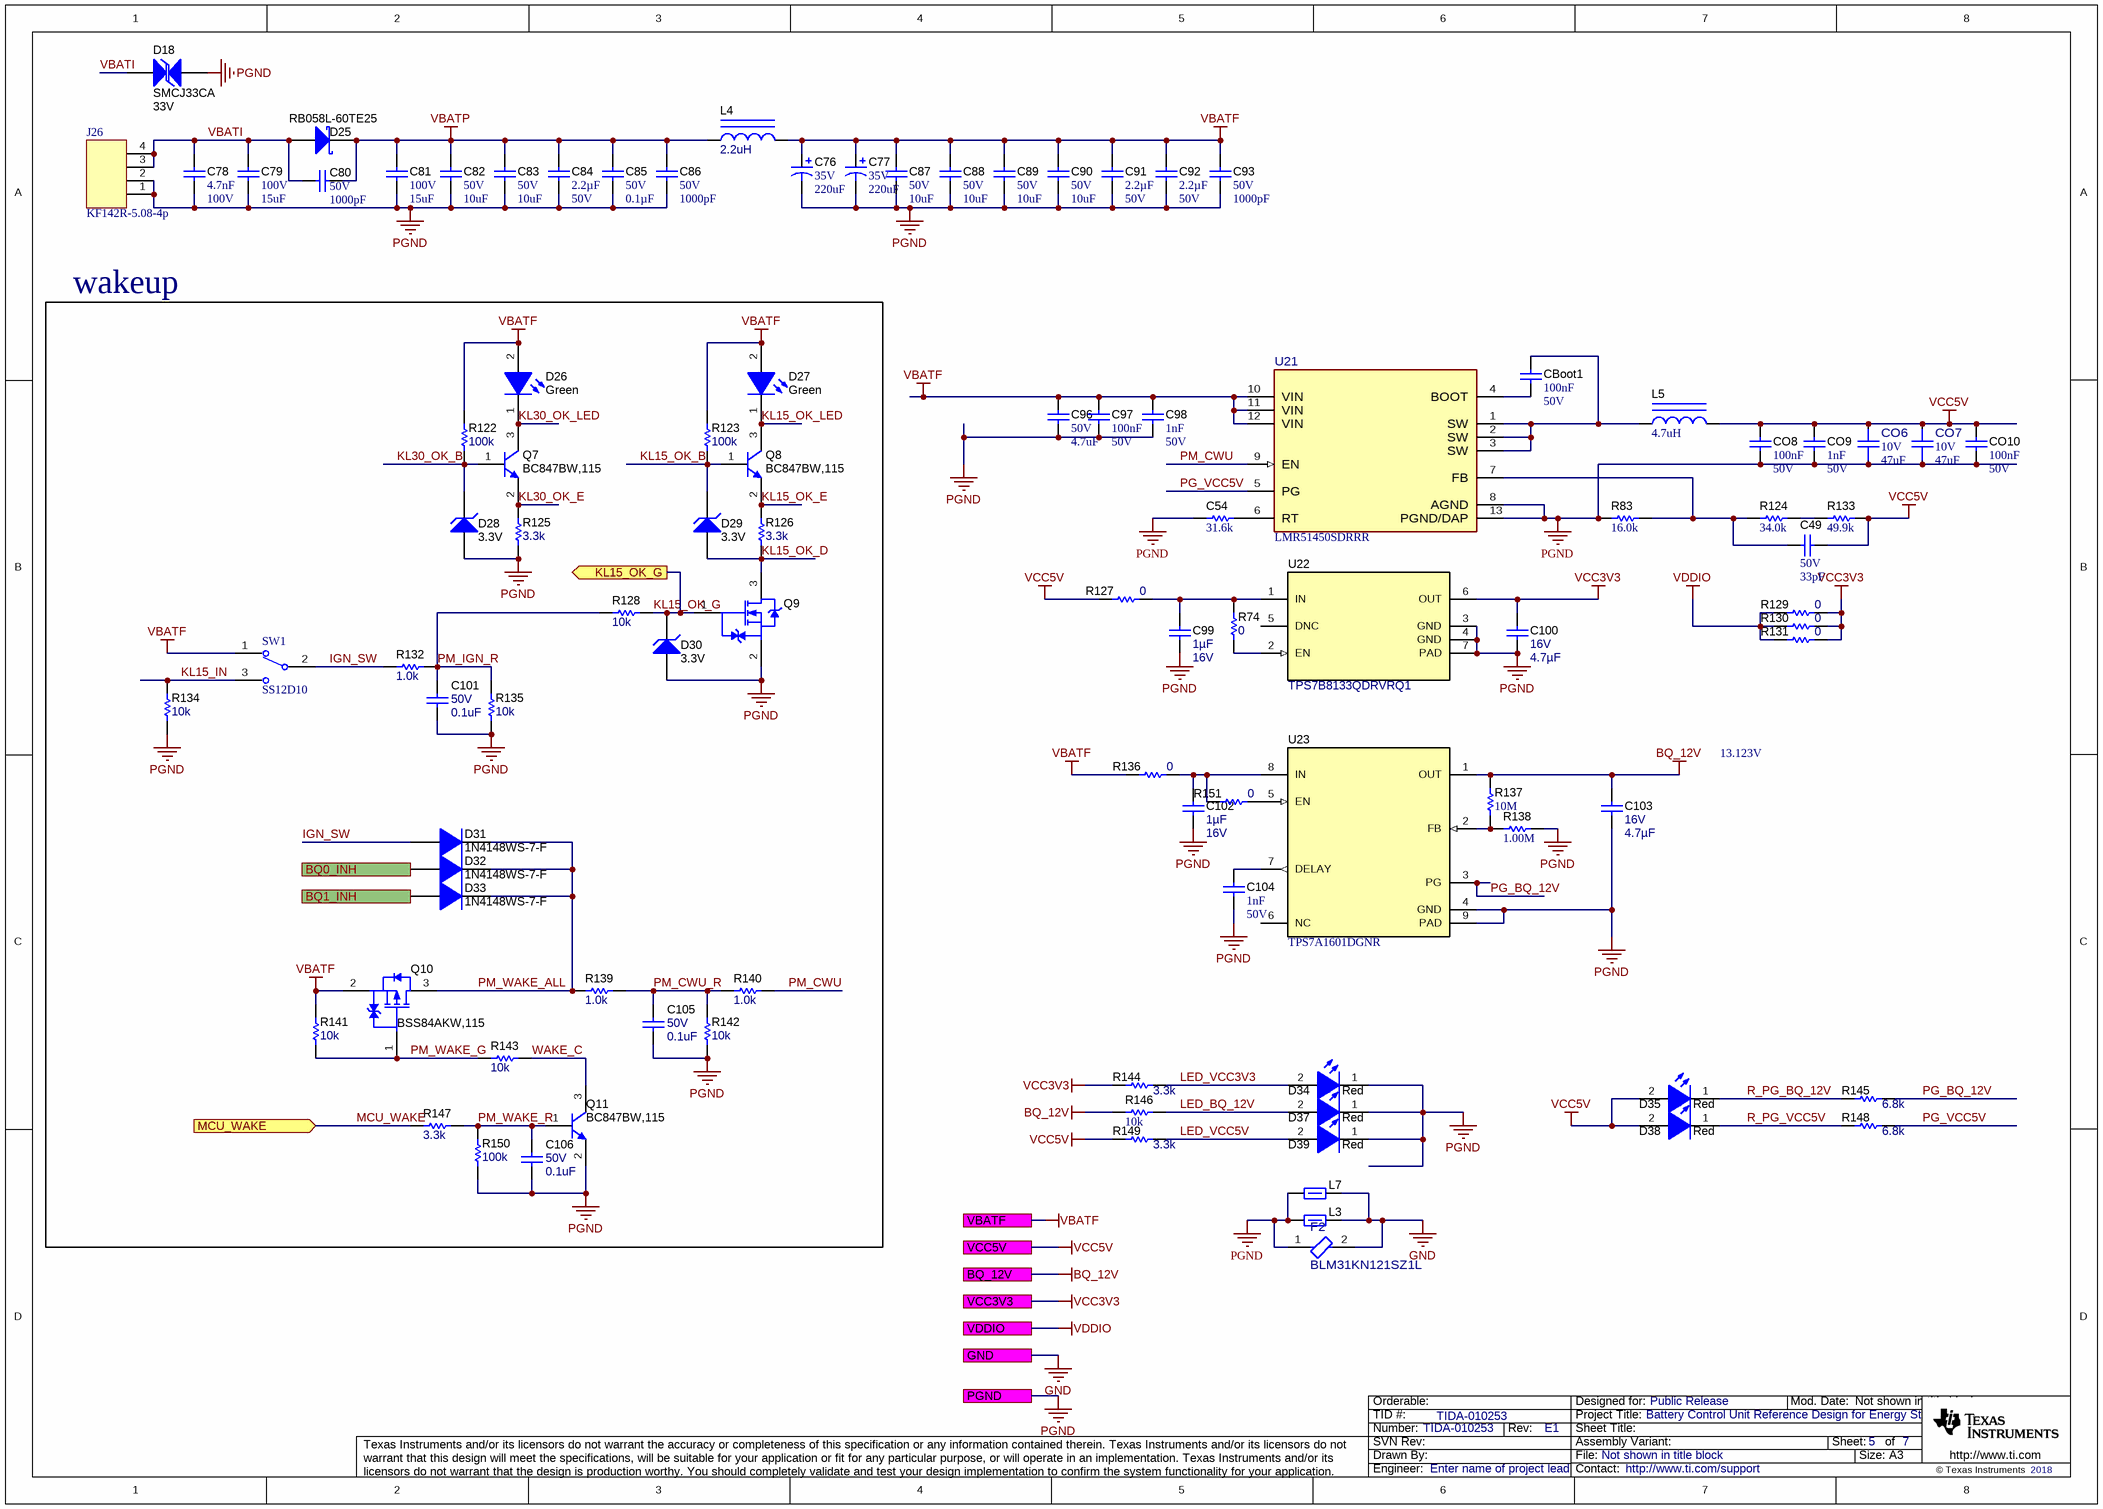
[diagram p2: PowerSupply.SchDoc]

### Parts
C49  VDC_V: 50V  ValueDisplayed: 33pF  [0603]  (hidden comment: 06035A330JAT2A)
C54  ValueDisplayed: 31.6k  [0603]  (hidden comment: CRCW060331K6FKEA)
C76  VDC_V: 35V  ValueDisplayed: 220uF  [SM_RADIAL_G]  (hidden comment: EEE-TP1V221AP)
C77  VDC_V: 35V  ValueDisplayed: 220uF  [SM_RADIAL_G]  (hidden comment: EEE-TP1V221AP)
C78  Cap_F: 4.7nF  VDC_V: 100V  [0603]  (hidden comment: CGA3E2X7R2A472K080AA)
C79  VDC_V: 100V  ValueDisplayed: 15uF  [2220_280]  (hidden comment: CGA9P3X7S2A156M250KB)
C80  VDC_V: 50V  ValueDisplayed: 1000pF  [0402]  (hidden comment: GRM1555C1H102JA01D)
C81  VDC_V: 100V  ValueDisplayed: 15uF  [2220_280]  (hidden comment: CGA9P3X7S2A156M250KB)
C82  VDC_V: 50V  ValueDisplayed: 10uF  [1210_280]  (hidden comment: CGA6P3X7S1H106K250AB)
C83  VDC_V: 50V  ValueDisplayed: 10uF  [1210_280]  (hidden comment: CGA6P3X7S1H106K250AB)
C84  Cap_F: 2.2µF  VDC_V: 50V  [0805_HV]  (hidden comment: CGA4J3X7R1H225K125AB)
C85  VDC_V: 50V  ValueDisplayed: 0.1µF  [0603]  (hidden comment: CGA3E3X8R1H104M080AB)
C86  VDC_V: 50V  ValueDisplayed: 1000pF  [0402]  (hidden comment: CGA2B2C0G1H102J050BA)
C87  VDC_V: 50V  ValueDisplayed: 10uF  [1210_280]  (hidden comment: CGA6P3X7S1H106K250AB)
C88  VDC_V: 50V  ValueDisplayed: 10uF  [1210_280]  (hidden comment: CGA6P3X7S1H106K250AB)
C89  VDC_V: 50V  ValueDisplayed: 10uF  [1210_280]  (hidden comment: CGA6P3X7S1H106K250AB)
C90  VDC_V: 50V  ValueDisplayed: 10uF  [1210_280]  (hidden comment: CGA6P3X7S1H106K250AB)
C91  Cap_F: 2.2µF  VDC_V: 50V  [0805_HV]  (hidden comment: CGA4J3X7R1H225K125AB)
C92  Cap_F: 2.2µF  VDC_V: 50V  [0805_HV]  (hidden comment: CGA4J3X7R1H225K125AB)
C93  VDC_V: 50V  ValueDisplayed: 1000pF  [0402]  (hidden comment: CGA2B2C0G1H102J050BA)
C96  VDC_V: 50V  ValueDisplayed: 4.7uF  [1210_280]  (hidden comment: CGA6P3X7R1H475K250AB)
C97  Cap_F: 100nF  VDC_V: 50V  [0805_HV]  (hidden comment: 08055C104JAT2A)
C98  Cap_F: 1nF  VDC_V: 50V  [0603]  (hidden comment: 885012206083)
C99  Cap_F: 1µF  VDC_V: 16V  [0603]  (hidden comment: GCM188R71C105KA64D)
C100  VDC_V: 16V  ValueDisplayed: 4.7µF  [0603]  (hidden comment: GRT188R61C475KE13D)
C101  VDC_V: 50V  ValueDisplayed: 0.1uF  [0402]  (hidden comment: GCM155R71H104KE02D)
C102  Cap_F: 1µF  VDC_V: 16V  [0603]  (hidden comment: GCM188R71C105KA64D)
C103  VDC_V: 16V  ValueDisplayed: 4.7µF  [0603]  (hidden comment: GRT188R61C475KE13D)
C104  Cap_F: 1nF  VDC_V: 50V  [0603]  (hidden comment: 885012206083)
C105  VDC_V: 50V  ValueDisplayed: 0.1uF  [0402]  (hidden comment: GCM155R71H104KE02D)
C106  VDC_V: 50V  ValueDisplayed: 0.1uF  [0402]  (hidden comment: GCM155R71H104KE02D)
CBoot1  Cap_F: 100nF  VDC_V: 50V  [0603]  (hidden comment: 06035C104KAT2A)
CO6  VDC_V: 10V  ValueDisplayed: 47uF  [FP-GRM32ER71A476ME15L_1210-MFG]  (hidden comment: GRM32ER71A476ME15L)
CO7  VDC_V: 10V  ValueDisplayed: 47uF  [FP-GRM32ER71A476ME15L_1210-MFG]  (hidden comment: GRM32ER71A476ME15L)
CO8  Cap_F: 100nF  VDC_V: 50V  [0805_HV]  (hidden comment: 08055C104JAT2A)
CO9  Cap_F: 1nF  VDC_V: 50V  [0603]  (hidden comment: 885012206083)
CO10  Cap_F: 100nF  VDC_V: 50V  [0805_HV]  (hidden comment: 08055C104JAT2A)
D18  SMCJ33CA  value 33V  [SMC_Bi]
D25  RB058L-60TE25  [SMA]
D26  value Green  [WL-SMCW_GREEN]  (hidden comment: 150060VS75000)
D27  value Green  [WL-SMCW_GREEN]  (hidden comment: 150060VS75000)
D28  value 3.3V  [SOD-323]  (hidden comment: SZMM3Z3V3ST1G)
D29  value 3.3V  [SOD-323]  (hidden comment: SZMM3Z3V3ST1G)
D30  value 3.3V  [SOD-323]  (hidden comment: SZMM3Z3V3ST1G)
D31  1N4148WS-7-F  [SOD-323]
D32  1N4148WS-7-F  [SOD-323]
D33  1N4148WS-7-F  [SOD-323]
D34  value Red  [WL-SMCW_RED]  (hidden comment: 150060RS75000)
D35  value Red  [WL-SMCW_RED]  (hidden comment: 150060RS75000)
D37  value Red  [WL-SMCW_RED]  (hidden comment: 150060RS75000)
D38  value Red  [WL-SMCW_RED]  (hidden comment: 150060RS75000)
D39  value Red  [WL-SMCW_RED]  (hidden comment: 150060RS75000)
F2  BLM31KN121SZ1L  [FP-BLM31KN121SZ1L_1206-MFG]
J26  KF142R-5.08-4p  [KF142R-5.08-4p]
L3  BLM18SG121TZ1D  [0603]  (value not drawn)
L4  ValueDisplayed: 2.2uH  [IHLP-2525CZ-5A]  (hidden comment: IHLP2525CZER2R2M5A)
L5  ValueDisplayed: 4.7uH  [WE-LHMI_1040]  (hidden comment: 74437368047)
L7  BLM18SG121TZ1D  [0603]  (value not drawn)
Q7  BC847BW,115  [SOT-323]
Q8  BC847BW,115  [SOT-323]
Q9  RJU003N03FRAT106  [SOT-323]  (value not drawn)
Q10  BSS84AKW,115  [SOT-323]
Q11  BC847BW,115  [SOT-323]
R74  ValueDisplayed: 0  [0603]  (hidden comment: CRCW06030000Z0EA)
R83  ValueDisplayed: 16.0k  [0603]  (hidden comment: RC0603FR-0716KL)
R122  ValueDisplayed: 100k  [0402]  (hidden comment: CRCW0402100KJNED)
R123  ValueDisplayed: 100k  [0402]  (hidden comment: CRCW0402100KJNED)
R124  ValueDisplayed: 34.0k  [0603]  (hidden comment: RC0603FR-0734KL)
R125  ValueDisplayed: 3.3k  [0402]  (hidden comment: CRCW04023K30JNED)
R126  ValueDisplayed: 3.3k  [0402]  (hidden comment: CRCW04023K30JNED)
R127  ValueDisplayed: 0  [0603]  (hidden comment: CRCW06030000Z0EA)
R128  ValueDisplayed: 10k  [0402]  (hidden comment: CRCW040210K0JNED)
R129  ValueDisplayed: 0  [0603]  (hidden comment: CRCW06030000Z0EA)
R130  ValueDisplayed: 0  [0603]  (hidden comment: CRCW06030000Z0EA)
R131  ValueDisplayed: 0  [0603]  (hidden comment: CRCW06030000Z0EA)
R132  ValueDisplayed: 1.0k  [0402]  (hidden comment: CRCW04021K00JNED)
R133  ValueDisplayed: 49.9k  [0603]  (hidden comment: RC0603FR-0749K9L)
R134  ValueDisplayed: 10k  [0402]  (hidden comment: CRCW040210K0JNED)
R135  ValueDisplayed: 10k  [0402]  (hidden comment: CRCW040210K0JNED)
R136  ValueDisplayed: 0  [0603]  (hidden comment: CRCW06030000Z0EA)
R137  ValueDisplayed: 10M  [0603]  (hidden comment: CRCW060310M0DHEAP)
R138  ValueDisplayed: 1.00M  [0603]  (hidden comment: CRCW06031M00DHEAP)
R139  ValueDisplayed: 1.0k  [0402]  (hidden comment: CRCW04021K00JNED)
R140  ValueDisplayed: 1.0k  [0402]  (hidden comment: CRCW04021K00JNED)
R141  ValueDisplayed: 10k  [0402]  (hidden comment: CRCW040210K0JNED)
R142  ValueDisplayed: 10k  [0402]  (hidden comment: CRCW040210K0JNED)
R143  ValueDisplayed: 10k  [0402]  (hidden comment: CRCW040210K0JNED)
R144  ValueDisplayed: 3.3k  [0402]  (hidden comment: CRCW04023K30JNED)
R145  ValueDisplayed: 6.8k  [0402]  (hidden comment: CRCW04026K80JNED)
R146  ValueDisplayed: 10k  [0402]  (hidden comment: CRCW040210K0JNED)
R147  ValueDisplayed: 3.3k  [0402]  (hidden comment: CRCW04023K30JNED)
R148  ValueDisplayed: 6.8k  [0402]  (hidden comment: CRCW04026K80JNED)
R149  ValueDisplayed: 3.3k  [0402]  (hidden comment: CRCW04023K30JNED)
R150  ValueDisplayed: 100k  [0402]  (hidden comment: CRCW0402100KJNED)
R151  ValueDisplayed: 0  [0603]  (hidden comment: CRCW06030000Z0EA)
SW1  SS12D10  [SS12D10]
U21  LMR51450SDRRR  [DRR0012E-MFG]
U22  TPS7B8133QDRVRQ1  [DRV0006A]
U23  TPS7A1601DGNR  [DGN0008C_N]

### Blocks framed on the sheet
wakeup: C101 C105 C106 D26-D33 Q7-Q11 R122 R123 R125 R126 R128 R132 R134 R135 R139-R143 R147 R150 SW1

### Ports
BQ0_INH (in), BQ1_INH (in), BQ_12V, GND, KL15_OK_G (out), MCU_WAKE (in), PGND, VBATF, VCC3V3, VCC5V, VDDIO

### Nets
BQ_12V: C103.1 R137.2 R146.1 U23.1(OUT) ; port BQ_12V
GND: F2.2 L3.2 L7.2 ; port GND
PGND: C54.1 C76.2(-) C77.2(-) C78.2 C79.2 C81.2 C82.2 C83.2 C84.2 C85.2 C86.2 C87.2 C88.2 C89.2 C90.2 C91.2 C92.2 C93.2 C96.2 C97.2 C98.2 C99.2 C100.2 C101.2 C102.2 C103.2 C104.2 C105.2 C106.2 CO6.1 CO7.1 CO8.2 CO9.2 CO10.2 D18.1 D28.2(A) D30.2(A) D34.1(K) D37.1(K) D39.1(K) F2.1 J26.1 J26.2 L3.1 L7.1 Q9.2(S) Q11.2(E) R83.2 R125.1 R134.1 R135.1 R138.1 R142.1 R150.1 U21.8(AGND) U21.13(PGND/DAP) U22.3(GND) U22.4(GND) U22.7(PAD) U23.4(GND) U23.9(PAD) ; port PGND
VBATF: C76.1(+) C77.1(+) C87.1 C88.1 C89.1 C90.1 C91.1 C92.1 C93.1 C96.1 C97.1 C98.1 D26.2(A) D27.2(A) L4.2 Q10.2(S) R122.2 R123.2 R136.1 R141.2 SW1.1 U21.10(VIN) U21.11(VIN) U21.12(VIN) ; port VBATF
VBATP: C80.1 C81.1 C82.1 C83.1 C84.1 C85.1 C86.1 D25.1(K) L4.1
VCC3V3: C100.1 R129.2 R130.2 R131.2 R144.1 U22.6(OUT) ; port VCC3V3
VCC5V: C49.1 CO6.2 CO7.2 CO8.1 CO9.1 CO10.1 D35.2(A) D38.2(A) L5.2 R127.1 R133.2 R149.1 ; port VCC5V
VDDIO: R129.1 R130.1 R131.1 ; port VDDIO
BQ0_INH: D32.2(A) ; port BQ0_INH
BQ1_INH: D33.2(A) ; port BQ1_INH
IGN_SW: D31.2(A) R132.1 SW1.2(2(COM))
KL15_IN: R134.2 SW1.3
KL15_OK_B: D29.1(K) Q8.1(B) R123.1
KL15_OK_D: D29.2(A) Q9.3(D) R126.1
KL15_OK_E: Q8.2(E) R126.2
KL15_OK_G: D30.1(K) Q9.1(G) R128.1 ; port KL15_OK_G
KL15_OK_LED: D27.1(K) Q8.3(C)
KL30_OK_B: D28.1(K) Q7.1(B) R122.1
KL30_OK_E: Q7.2(E) R125.2
KL30_OK_LED: D26.1(K) Q7.3(C)
LED_BQ_12V: D37.2(A) R146.2
LED_VCC3V3: D34.2(A) R144.2
LED_VCC5V: D39.2(A) R149.2
MCU_WAKE: R147.1 ; port MCU_WAKE
PG_BQ_12V: R145.2 U23.3(PG)
PG_VCC5V: R148.2 U21.5(PG)
PM_CWU: R140.2 U21.9(EN)
PM_CWU_R: C105.1 R139.2 R140.1 R142.2
PM_IGN_R: C101.1 R128.2 R132.2 R135.2
PM_WAKE_ALL: D31.1(K) D32.1(K) D33.1(K) Q10.3(D) R139.1
PM_WAKE_G: Q10.1(G) R141.1 R143.2
PM_WAKE_R: C106.1 Q11.1(B) R147.2 R150.2
R_PG_BQ_12V: D35.1(K) R145.1
R_PG_VCC5V: D38.1(K) R148.1
VBATI: C78.1 C79.1 C80.2 D18.2 D25.2(A) J26.3 J26.4
WAKE_C: Q11.3(C) R143.1
NetC49_2: C49.2 R83.1 R124.1 U21.7(FB)
NetC54_2: C54.2 U21.6(RT)
NetC99_1: C99.1 R74.2 R127.2 U22.1(IN)
NetC102_1: C102.1 R136.2 R151.1 U23.8(IN)
NetC104_1: C104.1 U23.7(DELAY)
NetCBoot1_1: CBoot1.1 L5.1 U21.1(SW) U21.2(SW) U21.3(SW)
NetCBoot1_2: CBoot1.2 U21.4(BOOT)
NetR74_1: R74.1 U22.2(EN)
NetR124_2: R124.2 R133.1
NetR137_1: R137.1 R138.2 U23.2(FB)
NetR151_2: R151.2 U23.5(EN)

Not connected (* = marked no-connect by the designer): U22 5(DNC); U23 6(NC)

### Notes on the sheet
- 13.123V

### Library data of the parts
C49 = CMP-0006783-4: CAP, CERM, 33 pF, 50 V, +/- 5%, C0G/NP0, 0603; Manufacturer: AVX; TaMin_C: -55°C; ESR_ohm: 2.09d; Polarized: N; SizeAreaWB_mm2: 4.68; Value1: 0.209 ohm; U/M: EA; Value: 33pF; TaMax_C: 125°C; SizeZ_mm: 1; SizeX_mm: 1.6; SizeY_mm: 0.8; SizeArea_mm2: 1.28; AEC Category: Q200
C54 = CMP-0022330-4: RES, 31.6 k, 1%, 0.1 W, AEC-Q200 Grade 0, 0603; Manufacturer: Vishay-Dale; Power_W: 100mW; TempCo: 100 ppm/C; Value_Code: 31k6; Value: 31.6k; EIA_Code: E96; SizeX_mm: 1.6; SizeY_mm: 0.8; SizeZ_mm: 1; Value2: 0.1W; SizeArea_mm2: 1.28; AEC Qualified: Y; VDC_V: 75V; AEC Category: Q200; AEC Grade: 0
C76 C77 = CMP-0010742-1: CAP, AL, 220 uF, 35 V, +/- 20%, 0.15 ohm, AEC-Q200 Grade 1, SMD; Manufacturer: Panasonic; TaMin_C: -40°C; ESR_ohm: 1.5d; Polarized: Y; SizeAreaWB_mm2: 172.2; U/M: EA; Value: 220uF; TaMax_C: 125°C; SizeZ_mm: 10.2; SizeX_mm: 12; SizeY_mm: 10.3; Cap_Case: 10x10.2mm; SizeArea_mm2: 123.6; CompType: Capacitor; Cap_F: 220µF; IRMS_A: 5dA; AEC Grade: 1; AEC Category: Q200
C78 = CMP-0007088-4: CAP, CERM, 4700 pF, 100 V, +/- 10%, X7R, AEC-Q200 Grade 1, 0603; Manufacturer: TDK; TaMin_C: -55°C; ESR_ohm: 0.469862; Polarized: N; SizeAreaWB_mm2: 4.68; Value1: 0.469862 ohm; U/M: EA; Value: 4700pF; TaMax_C: 125°C; SizeZ_mm: 1; SizeX_mm: 1.6; SizeY_mm: 0.8; SizeArea_mm2: 1.28; AEC Qualified: Y; IRMS_A: 323.35mA; AEC Category: Q200
C79 C81 = CMP-0009420-2: CAP, CERM, 15 uF, 100 V, +/- 20%, X7S, AEC-Q200 Grade 1, 2220; Manufacturer: TDK; TaMin_C: -55°C; ESR_ohm: 2.642m; Polarized: N; SizeAreaWB_mm2: 53.9; Value1: 0.002642 ohm; U/M: EA; Value: 15uF; TaMax_C: 125°C; SizeZ_mm: 2.8; SizeX_mm: 5.7; SizeY_mm: 5; SizeArea_mm2: 28.5; AEC Qualified: Y; Cap_F: 15µF; IRMS_A: 5.61617A; AEC Grade: 1; AEC Category: Q200
C80 = CMP-0006412-2: CAP, CERM, 1000 pF, 50 V, +/- 5%, C0G/NP0, 0402; Manufacturer: MuRata; TaMin_C: -55°C; Polarized: N; SizeAreaWB_mm2: 3; Value1: Unknown; U/M: EA; Value: 1000pF; TaMax_C: 125°C; SizeZ_mm: 0.6; SizeX_mm: 1; SizeY_mm: 0.5; Cap_F: 1nF; AEC Category: Q200
C82 C83 C87-C90 = CMP-0009164-2: CAP, CERM, 10 uF, 50 V, +/- 10%, X7S, AEC-Q200 Grade 1, 1210; Manufacturer: TDK; TaMin_C: -55°C; ESR_ohm: 2.827m; Polarized: N; SizeAreaWB_mm2: 14.7; Value1: 0.002827 ohm; U/M: EA; Value: 10uF; TaMax_C: 125°C; SizeZ_mm: 2.8; SizeX_mm: 3.2; SizeY_mm: 2.5; SizeArea_mm2: 8; AEC Qualified: Y; Cap_F: 10µF; IRMS_A: 4.37286A; AEC Grade: 1; AEC Category: Q200
C84 C91 C92 = CMP-0007977-2: CAP, CERM, 2.2 uF, 50 V, +/- 10%, X7R, AEC-Q200 Grade 1, 0805; Manufacturer: TDK; TaMin_C: -55°C; ESR_ohm: 3.288m; Polarized: N; SizeAreaWB_mm2: 6.75; Value1: 0.003288 ohm; U/M: EA; Value: 2.2uF; TaMax_C: 125°C; SizeZ_mm: 1.45; SizeX_mm: 2; SizeY_mm: 1.25; Cap_Case: 0805; SizeArea_mm2: 2.5; AEC Qualified: Y; IRMS_A: 3.60029A; AEC Grade: 1; AEC Category: Q200
C85 = CMP-0084240-1: CAP, CERM, 0.1 µF, 50 V,+/- 20%, X8R, AEC-Q200 Grade 0, 0603; Manufacturer: TDK; TaMin_C: -55°C; Polarized: N; SizeAreaWB_mm2: 4.68; U/M: EA; Value: 0.1uF; TaMax_C: 150°C; SizeZ_mm: 1; SizeX_mm: 1.6; SizeY_mm: 0.8; SizeArea_mm2: 1.28; AEC Qualified: Y; Cap_F: 100nF; AEC Grade: 0; AEC Category: Q200
C86 C93 = CMP-0006309-2: CAP, CERM, 1000 pF, 50 V, +/- 5%, C0G/NP0, AEC-Q200 Grade 1, 0402; Manufacturer: TDK; TaMin_C: -55°C; Polarized: N; SizeAreaWB_mm2: 3; Value1: Unknown; U/M: EA; Value: 1000pF; TaMax_C: 125°C; SizeZ_mm: 0.6; SizeX_mm: 1; SizeY_mm: 0.5; AEC Qualified: Y; Cap_F: 1nF; AEC Category: Q200
C96 = CMP-0009162-2: CAP, CERM, 4.7 uF, 50 V, +/- 10%, X7R, AEC-Q200 Grade 1, 1210; Manufacturer: TDK; TaMin_C: -55°C; ESR_ohm: 3.166m; Polarized: N; SizeAreaWB_mm2: 14.7; Value1: 0.003166 ohm; U/M: EA; Value: 4.7uF; TaMax_C: 125°C; SizeZ_mm: 2.8; SizeX_mm: 3.2; SizeY_mm: 2.5; SizeArea_mm2: 8; AEC Qualified: Y; Cap_F: 4.7µF; IRMS_A: 4.13311A; AEC Grade: 1; AEC Category: Q200
C97 CO8 CO10 = CMP-0007631-2: CAP, CERM, 0.1 uF, 50 V, +/- 5%, X7R, 0805; Manufacturer: AVX; TaMin_C: -55°C; ESR_ohm: 0.024; Polarized: N; SizeAreaWB_mm2: 6.75; Value1: 0.024 ohm; U/M: EA; Value: 0.1uF; TaMax_C: 125°C; SizeZ_mm: 1.45; SizeX_mm: 2; SizeY_mm: 1.25; Cap_Case: 0805; SizeArea_mm2: 2.5; AEC Category: Q200
C98 C104 CO9 = CMP-0064933-4: CAP, CERM, 1000 pF, 50 V,+/- 10%, X7R, 0603; Manufacturer: Wurth Elektronik; TaMin_C: -55°C; Polarized: N; SizeAreaWB_mm2: 4.68; Value1: Unknown; U/M: EA; Value: 1000pF; TaMax_C: 125°C; SizeZ_mm: 1; SizeX_mm: 1.6; SizeY_mm: 0.8; SizeArea_mm2: 1.28; AEC Category: Q200
C99 C102 = CMP-0007136-5: CAP, CERM, 1 uF, 16 V, +/- 10%, X7R, AEC-Q200 Grade 1, 0603; Manufacturer: MuRata; TaMin_C: -55°C; Polarized: N; SizeAreaWB_mm2: 4.68; Value1: Unknown; U/M: EA; Value: 1uF; TaMax_C: 125°C; SizeZ_mm: 1; SizeX_mm: 1.6; SizeY_mm: 0.8; SizeArea_mm2: 1.28; AEC Qualified: Y; AEC Category: Q200
C100 C103 = CMP-0081052-1: CAP, CERM, 4.7 µF, 16 V,+/- 10%, X5R, AEC-Q200 Grade 3, 0603; Manufacturer: MuRata; SizeAreaWB_mm2: 4.68; SizeArea_mm2: 1.28; AEC Qualified: Y; AEC Category: Q200; Value: 4.7uF; TaMax_C: 85°C; SizeZ_mm: 1; AEC Grade: 3; Polarized: N; TaMin_C: -55°C; SizeY_mm: 0.8; U/M: EA; SizeX_mm: 1.6
C101 C105 C106 = CMP-0006356-2: as C19 on sheet DaisyChain
CBoot1 = CMP-0006802-4: CAP, CERM, 0.1 uF, 50 V, +/- 10%, X7R, 0603; Manufacturer: AVX; TaMin_C: -55°C; Polarized: N; SizeAreaWB_mm2: 4.68; Value1: Unknown; U/M: EA; Value: 0.1uF; TaMax_C: 125°C; SizeZ_mm: 1; SizeX_mm: 1.6; SizeY_mm: 0.8; SizeArea_mm2: 1.28; AEC Category: Q200
CO6 CO7 = CMP-0088887-1: 47µF ±20% 10V Ceramic Capacitor X7R 1210 (3225 Metric); Manufacturer: Murata; AEC Qualified: No; TempCo: 15%; SizeZ_mm: 2.7mm
D18 = CMP-0005695-3: Diode, TVS, Bi, 33 V, SMC; Manufacturer: Bourns; SizeZ_mm: 2.6; Ppk: 1.5kW; Value1: 1500W; AEC Category: Q101; SizeArea_mm2: 50.5686; SizeX_mm: 8.13; SizeAreaWB_mm2: 83.2686; SizeY_mm: 6.22
D25 = CMP-0028854-2: Diode, Schottky, 60 V, 3 A, AEC-Q101, SMA; Manufacturer: Rohm; Value1: 3A; AEC Category: Q101; Green_REACh: Incomplete; TJmax_C: 150°C; SizeArea_mm2: 16.3228; Vf_V: 640mV; SizeZ_mm: 2.87; Value2: 0.64V; Value: 60V; SizeX_mm: 5.59; AEC Qualified: Y; Green_Lifecycle: Not Set; SizeAreaWB_mm2: 37.3428; SizeY_mm: 2.92
D26 D27 = CMP-0002894-2: as D10 on sheet DaisyChain
D28-D30 = CMP-0085730-1: as D9 on sheet DaisyChain
D31-D33 = CMP-0079597-2: Diode, Switching, 75 V, 0.15 A, AEC-Q101, SOD-323; Manufacturer: Diodes Inc.; SizeX_mm: 2.7; Vf_V: 1.25V; AEC Qualified: Y; SizeArea_mm2: 3.645; AEC Category: Q101; SizeAreaWB_mm2: 8.695; Io_A: 150mA; SizeZ_mm: 1; Value1: 0.15A; SizeY_mm: 1.35; TJmax_C: 150°C; Vr_V: 75V; Value: 75V
D34 D35 D37-D39 = CMP-0002947-3: as D11 on sheet DaisyChain
F2 = CMP-0091575-1: Chip Ferrite Bead, 1206, 120Ω @ 100MHz, 0.009Ω, 25%, 6A; Manufacturer: Murata; SizeZ_mm: 1.8mm; DCR_ohm: 9m; AEC Grade: Grade 1; AEC Qualified: Yes
L3 L7 = CMP-0084877-1: Inductor, Ferrite Bead, Ferrite, 3 A, 120 ohm, AEC-Q200 Grade 1, SMD; Manufacturer: MuRata; SizeX_mm: 1.6; DCR_ohm: 120; AEC Grade: 1; Value2: 3A; Value1: 120 ohm; SizeY_mm: 0.8; SizeAreaWB_mm2: 4.68; SizeArea_mm2: 1.28; AEC Qualified: Y; AEC Category: Q200
L4 = CMP-0063383-1: Inductor, Shielded, 2.2 uH, 8.1 A, 0.0183 ohm, AEC-Q200 Grade 1, SMD; Manufacturer: Vishay-Dale; Isat: 10.8A @ 20% inductance drop; Irms: 8.1A @ 40C rise; Green_Lifecycle: Active; SizeAreaWB_mm2: 75.0442; DCR_ohm: 0.0183; Green_REACh: Passed; Value: 2.2uH; Imax_A: 8.1A; SizeZ_mm: 3; SizeX_mm: 6.86; SizeY_mm: 6.47; SizeArea_mm2: 44.3842; Ind_H: 2.2µH; AEC Qualified: Y; AEC Grade: 1; AEC Category: Q200
L5 = CMP-0064124-1: Inductor, Shielded Drum Core, Powdered Iron, 4.7 uH, 7 A, 0.015 ohm, SMD; Manufacturer: Wurth Elektronik; Isat: 19A @ 20% inductance drop; Irms: 7A @ 40C rise; Green_Lifecycle: Active; SizeAreaWB_mm2: 156; DCR_ohm: 0.015; Green_REACh: Passed; Value: 4.7uH; Imax_A: 7A; SizeZ_mm: 4; SizeX_mm: 11; SizeY_mm: 10; SizeArea_mm2: 110; Ind_H: 4.7µH; AEC Category: Q200
Q7 Q8 Q11 = CMP-0000486-2: Transistor, NPN, 45 V, 0.1 A, AEC-Q101, SOT-323; Manufacturer: NXP Semiconductor; TaMax_C: 150°C; Value2: 800; Value1: 0.1 A; Vcesat1_V: 90mV; SizeX_mm: 2.2; TaMin_C: -65°C; IcRated_A: 1dA; CompType: BJT; SizeZ_mm: 1.1; AEC Qualified: Y; Value: 45 V; SizeArea_mm2: 4.84; NPN: 1; Vceo_V: 45V; PNP: 0; AEC Category: Q101; SizeAreaWB_mm2: 10.24; U/M: EA
Q9 = CMP-0067562-1: as Q1 on sheet DaisyChain
Q10 = CMP-0000013-4: MOSFET, P-CH, -50 V, -0.15 A, AEC-Q101, SOT-323; Manufacturer: Nexperia; Alternate Manufacturer: None; AEC Category: Q101; SizeY_mm: 2.2; Value: -50V; ChMode: Enhancement; ChType: P; QgTyp_nC: 0.26; IdsMax_A: -150mA; Value2: 0.26 nC; SizeZ_mm: 1.1; SizeAreaWB_mm2: 10.24; AEC Qualified: Y; Vgs_V: -20V; SizeArea_mm2: 4.84
R74 R127 R129-R131 R136 R151 = CMP-0025697-4: as R71 on sheet DaisyChain
R83 = CMP-0022831-5: RES, 16.0 k, 1%, 0.1 W, 0603; Manufacturer: Yageo; Power_W: 100mW; TempCo: 100 ppm/C; Value_Code: 16k0; Value: 16.0k; Res_ohm: 16k; SizeX_mm: 1.6; SizeY_mm: 0.8; SizeZ_mm: 1; Value2: 0.1W; SizeArea_mm2: 1.28; AEC Qualified: N; VDC_V: 75V; AEC Category: Q200; SizeAreaWB_mm2: 4.68
R122 R123 R150 = CMP-0026823-3: as R42 on sheet DaisyChain
R124 = CMP-0023045-5: RES, 34.0 k, 1%, 0.1 W, 0603; Manufacturer: Yageo; Power_W: 100mW; TempCo: 100 ppm/C; Value_Code: 34k0; Value: 34.0k; EIA_Code: E96; Res_ohm: 34k; SizeX_mm: 1.6; SizeY_mm: 0.8; SizeZ_mm: 1; Value2: 0.1W; SizeArea_mm2: 1.28; AEC Qualified: N; VDC_V: 75V; AEC Category: Q200; SizeAreaWB_mm2: 4.68
R125 R126 R144 R147 R149 = CMP-0026918-5: as R52 on sheet DaisyChain
R128 R134 R135 R141-R143 R146 = CMP-0026825-5: as R41 on sheet DaisyChain
R132 R139 R140 = CMP-0026852-3: RES, 1.0 k, 5%, 0.063 W, AEC-Q200 Grade 0, 0402; Manufacturer: Vishay-Dale; Power_W: 63mW; TempCo: 200 ppm/C; Value_Code: 1k00; Value: 1.0k; EIA_Code: E24; Res_ohm: 1k; SizeX_mm: 1; SizeY_mm: 0.5; SizeZ_mm: 0.6; Value2: 0.063W; AEC Qualified: Y; VDC_V: 50V; AEC Category: Q200; AEC Grade: 0
R133 = CMP-0023142-5: RES, 49.9 k, 1%, 0.1 W, 0603; Manufacturer: Yageo; Power_W: 100mW; TempCo: 100 ppm/C; Value_Code: 49k9; Value: 49.9k; EIA_Code: E96; SizeX_mm: 1.6; SizeY_mm: 0.8; SizeZ_mm: 1; Value2: 0.1W; SizeArea_mm2: 1.28; AEC Qualified: N; VDC_V: 75V; AEC Category: Q200; SizeAreaWB_mm2: 4.68
R137 = CMP-0023358-4: RES, 10 M, 0.5%, 0.1 W, AEC-Q200 Grade 0, 0603; Manufacturer: Vishay-Dale; Power_W: 100mW; TempCo: 50 ppm/C; Value_Code: 10M0; Value: 10Meg; EIA_Code: E24; SizeX_mm: 1.6; SizeY_mm: 0.8; SizeZ_mm: 1; Value2: 0.1W; SizeArea_mm2: 1.28; AEC Qualified: Y; VDC_V: 75V; AEC Grade: 0; AEC Category: Q200
R138 = CMP-0082111-1: RES, 1.00 M, 0.5%, 0.1 W, AEC-Q200 Grade 0, 0603; Manufacturer: Vishay-Dale; Value_Code: 1M00; SizeAreaWB_mm2: 4.68; SizeArea_mm2: 1.28; AEC Qualified: Y; AEC Category: Q200; Res_ohm: 1M; Value: 1.00Meg; SizeZ_mm: 1; Green_REACh: Passed; EIA_Code: E192; TempCo: 50 ppm/C; AEC Grade: 0; Power_W: 100mW; VDC_V: 75V; SizeY_mm: 0.8; Value2: 0.1W; Green_Lifecycle: Active; SizeX_mm: 1.6
R145 R148 = CMP-0026966-5: RES, 6.8 k, 5%, 0.063 W, AEC-Q200 Grade 0, 0402; Manufacturer: Vishay-Dale; Power_W: 63mW; TempCo: 200 ppm/C; Value_Code: 6k80; Value: 6.8k; EIA_Code: E24; SizeX_mm: 1; SizeY_mm: 0.5; SizeZ_mm: 0.6; Value2: 0.063W; AEC Qualified: Y; VDC_V: 50V; AEC Category: Q200; AEC Grade: 0
U21 = CMP-0096683-1: 4-V to 36-V, 5-A Synchronous Step-Down DC/DC Converter with Low IQ; Manufacturer: Texas Instruments; Max Supply Voltage: 36V; TJmax_C: +150°C; Max Duty Cycle: 97%; Output Voltage: 1-16V; Nominal Supply Current: 25uA; Standoff Height: 0mm; Switching Topology: Buck; Number Of Outputs: 1; Output Type: AdjustableProgrammable; Switching Frequency: 200-1100kHz; SizeZ_mm: 0.8mm; AEC Qualified: No; Min Supply Voltage: 4V
U22 = CMP-0860463-2: Automotive 150-mA high-voltage ultra-low-IQ low-dropout (LDO) linear regulator, DRV0006A (WSON-6); Alternate Manufacturer: Texas Instruments; AEC Qualified: Y; SizeY_mm: 2; SizeZ_mm: 0.8; AEC Category: Q200; CompType: IC; SizeArea_mm2: 4; SizeAreaWB_mm2: 9
U23 = CMP-0035939-4: 60V, 5uA Iq, 100mA Low-Dropout (LDO) Voltage Regulator With Enable and Power Good, DGN0008C (VSSOP-8); Manufacturer: Texas Instruments; Alternate PartNumber: TPS7A1601DGNT; Iout(Max)(A): 0.1; Vout Adj(Min)(V): 1.2; Accuracy(%): 2; Vdo(Typ)(mV): 60; Power Good: TRUE; Vin(Min)(V): 3; Iq(Typ)(mA): 0.004; SubFamily: Single Channel LDO; Rating: Catalog; Vout Adj(Max)(V): 18.5; Eco-Plan: Green (RoHS & no Sb/Br); AEC Category: Q200; AEC Qualified: N; CompType: IC; SizeAreaWB_mm2: 23.6; SizeArea_mm2: 14.7; SizeX_mm: 4.9; SizeY_mm: 3.0; SizeZ_mm: 1.1; Green_Lifecycle: Active; Green_REACh: Passed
